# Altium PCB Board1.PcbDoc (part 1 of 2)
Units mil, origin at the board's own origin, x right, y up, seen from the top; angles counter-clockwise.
Board outline 6000 x 4000 mil, 8 copper layers (Top Layer, 3.3V, 2.5V, 1.8V, 1.0V, GND, signal2, Bottom Layer), stack 66.302 mil thick; 90 components, 131 nets, 720 pads, 306 vias.
Unrouted connection lines stored in the file: 162.
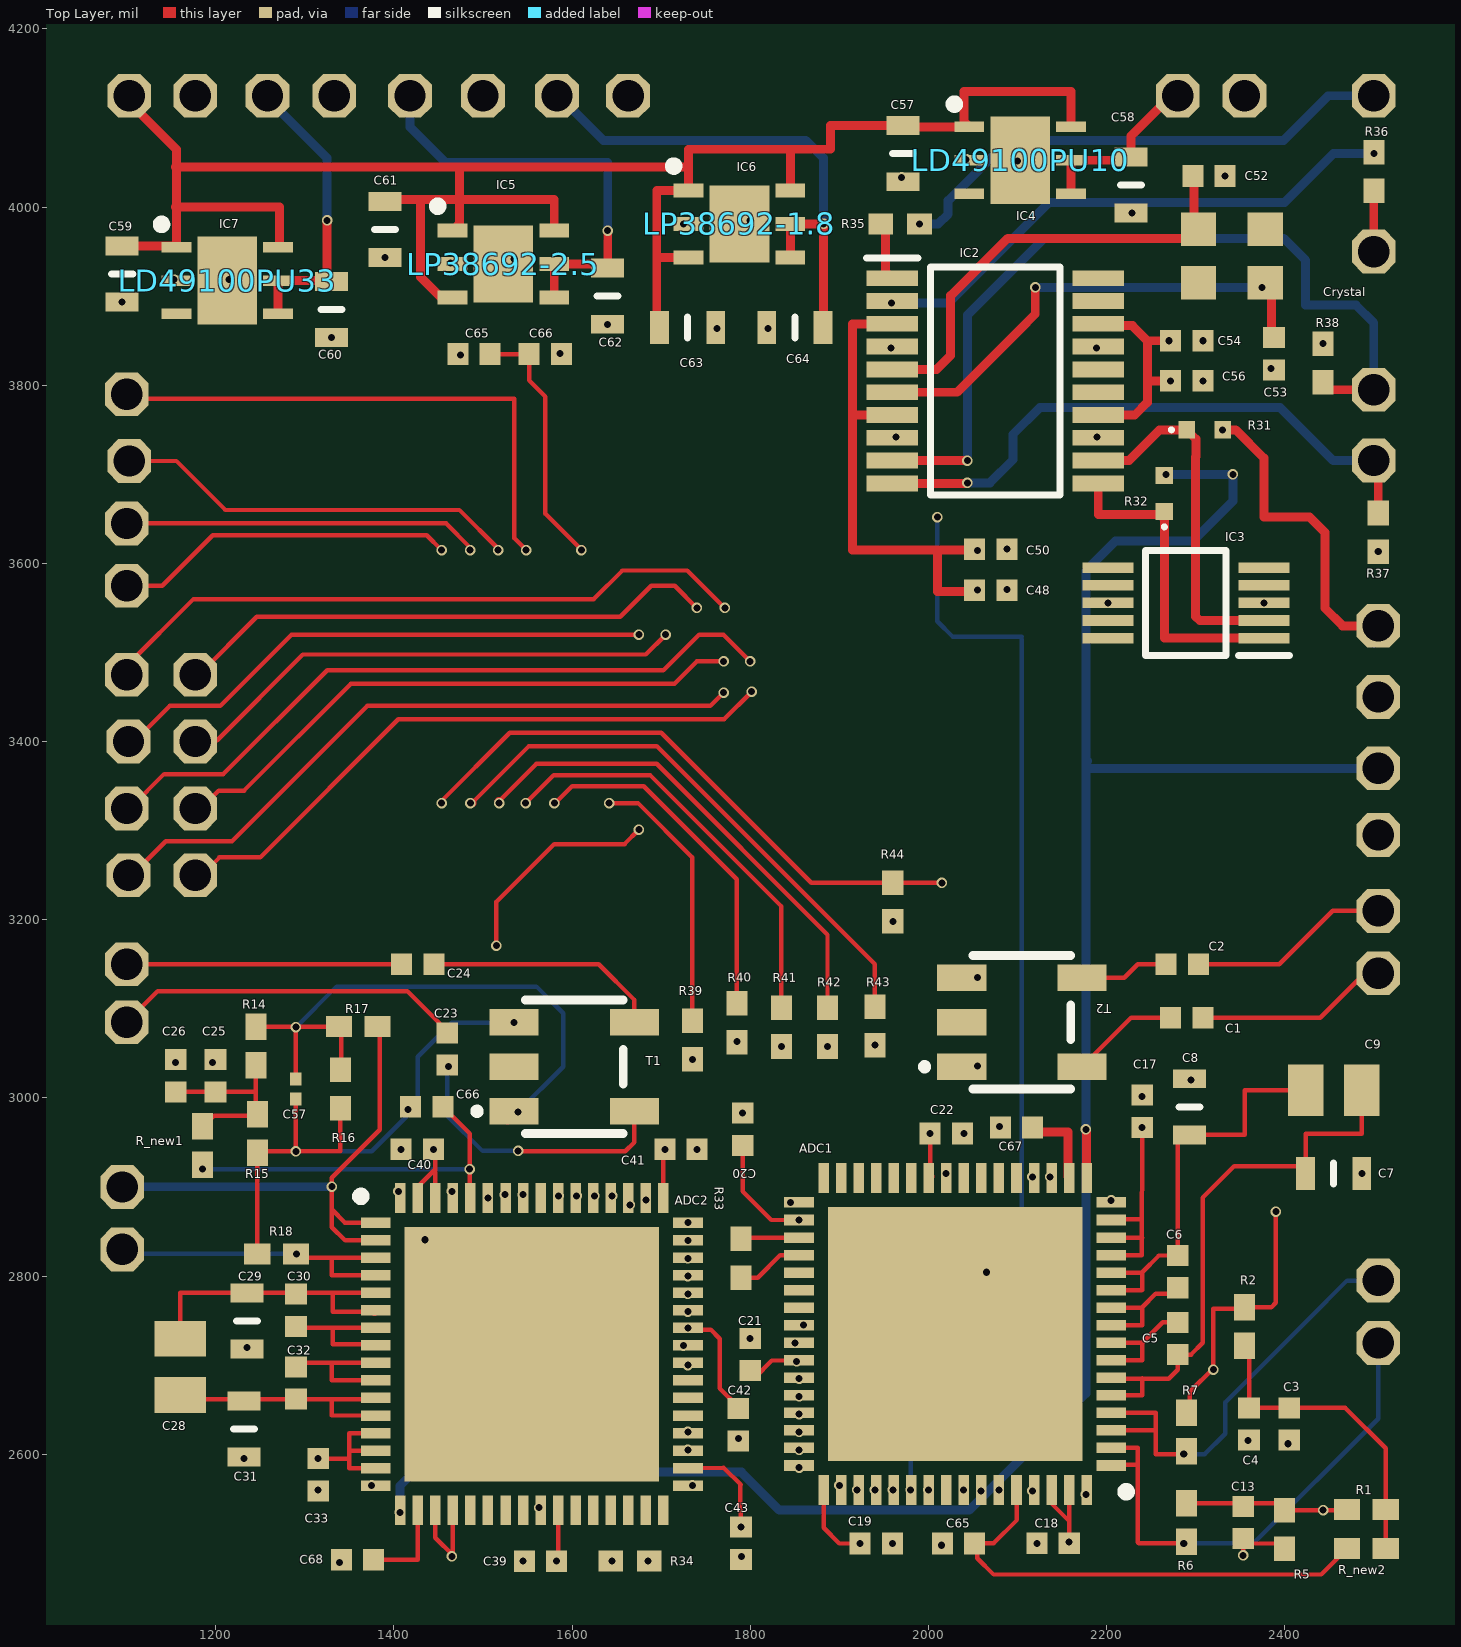
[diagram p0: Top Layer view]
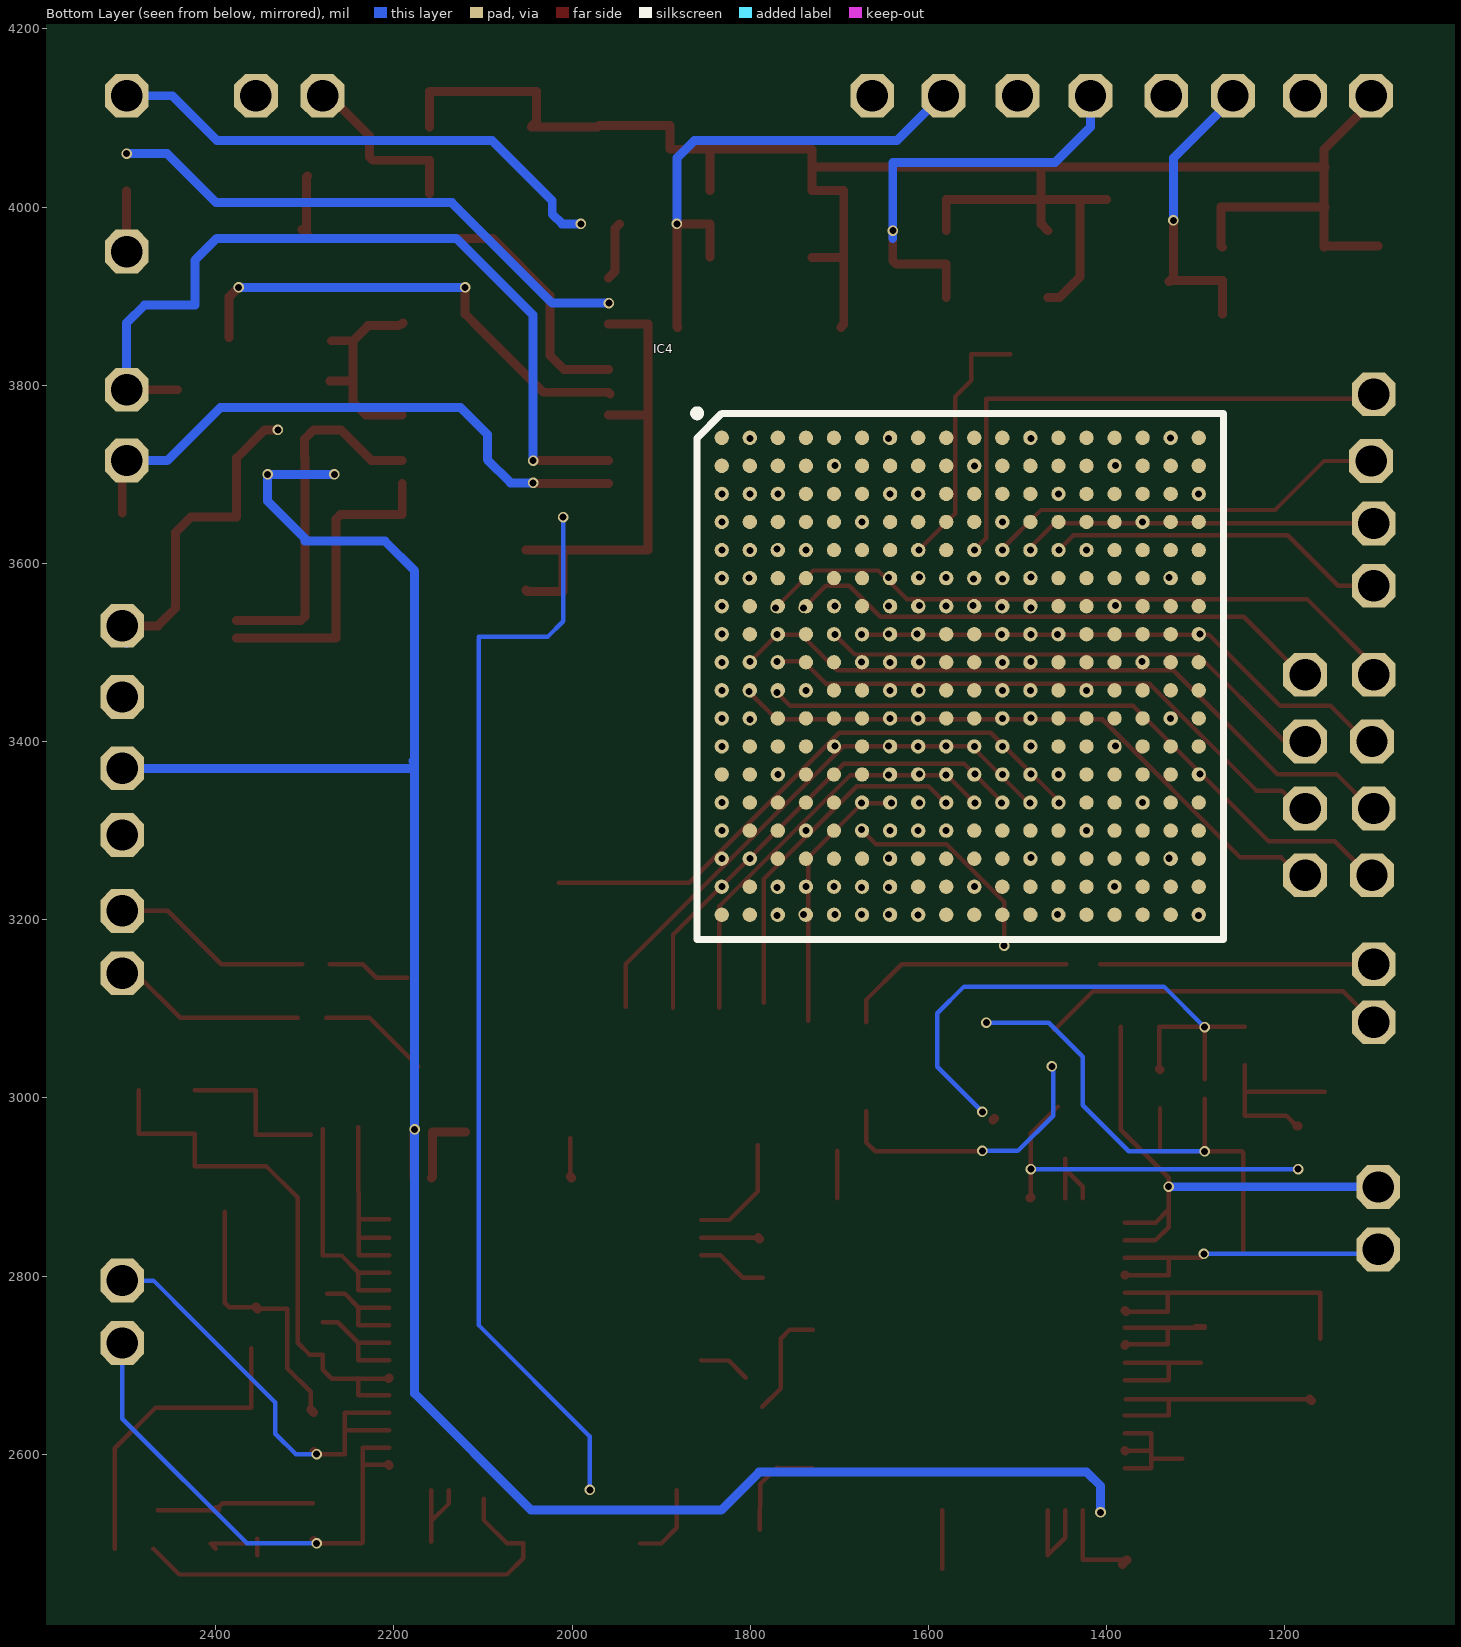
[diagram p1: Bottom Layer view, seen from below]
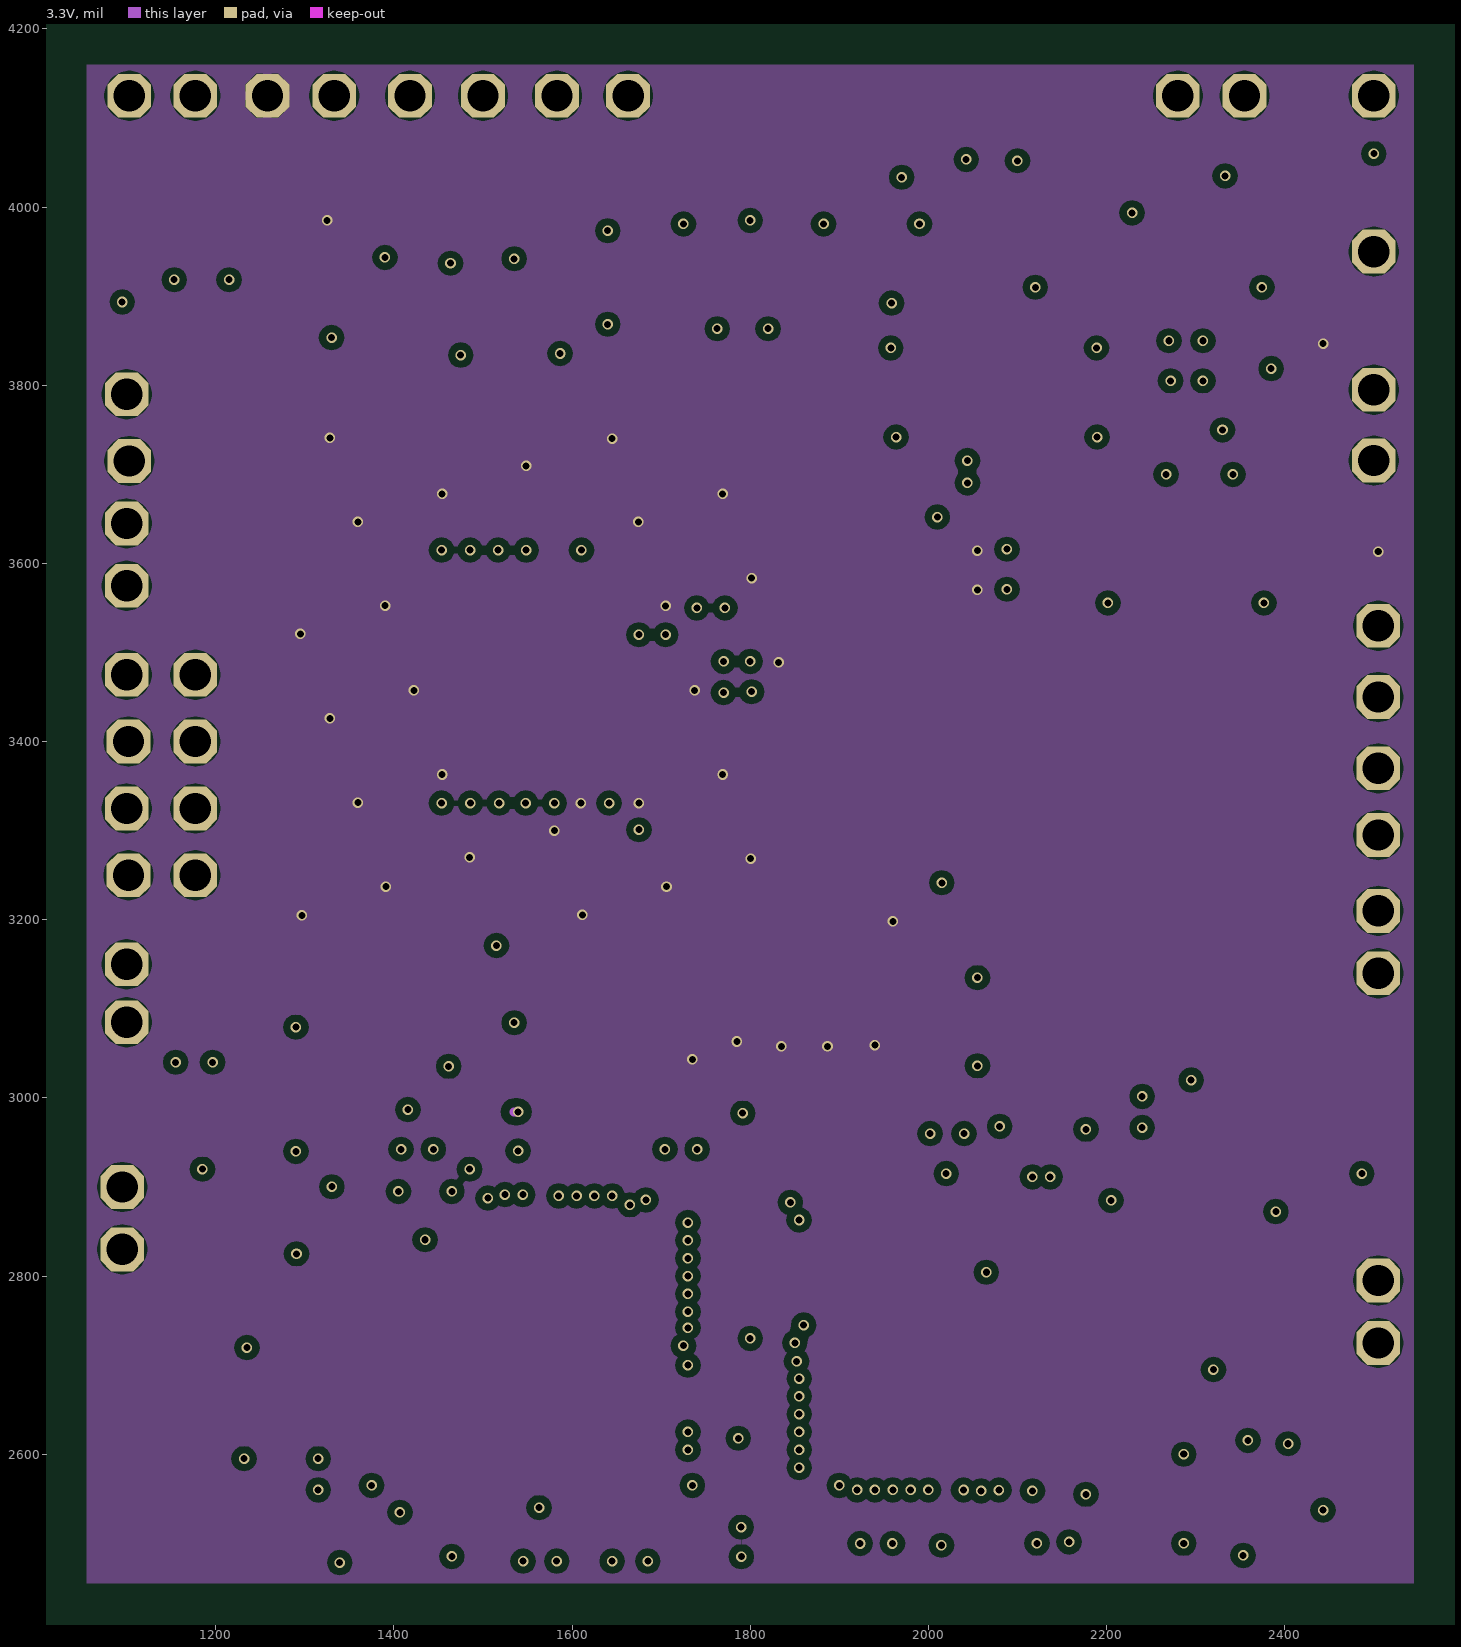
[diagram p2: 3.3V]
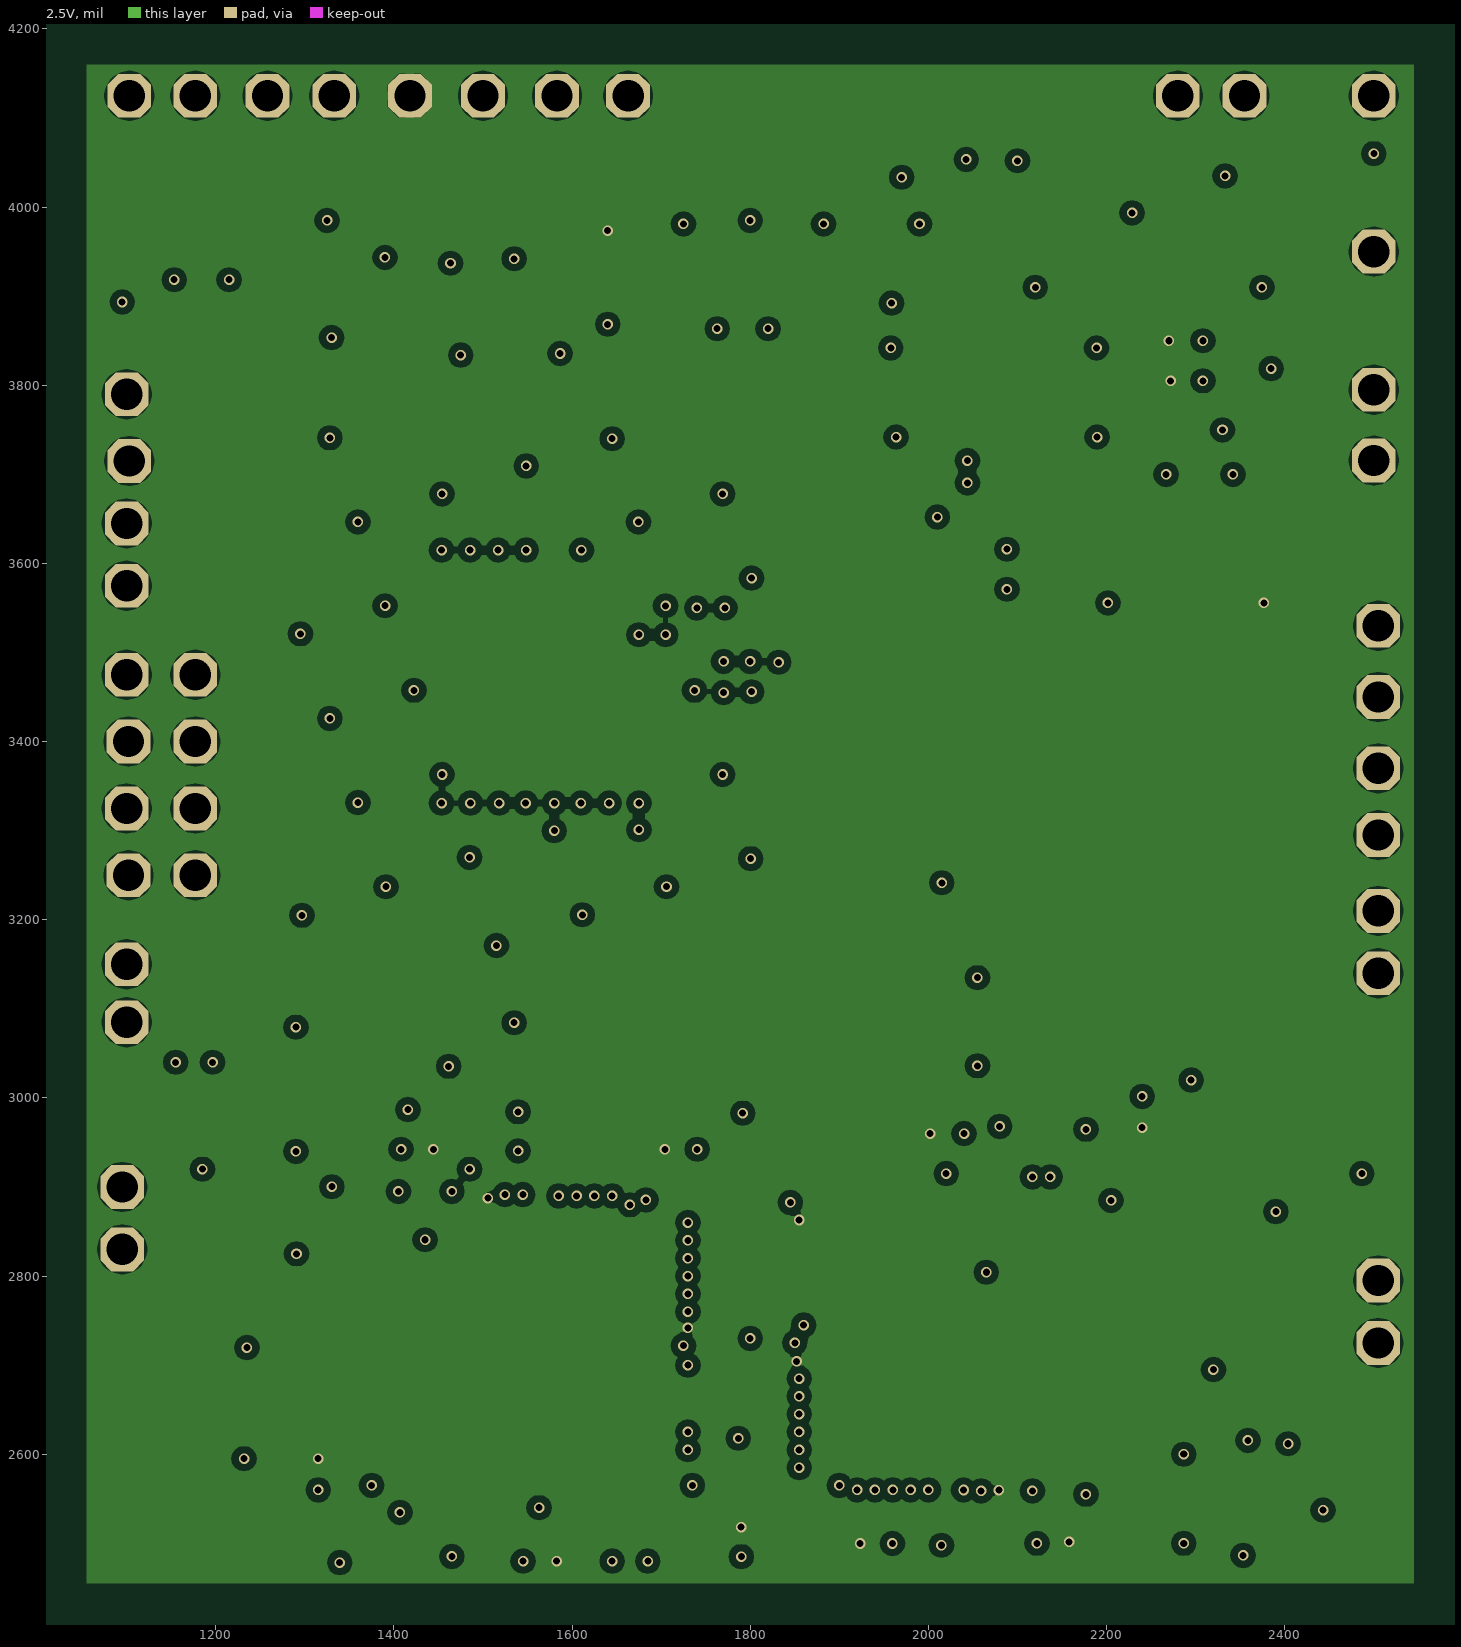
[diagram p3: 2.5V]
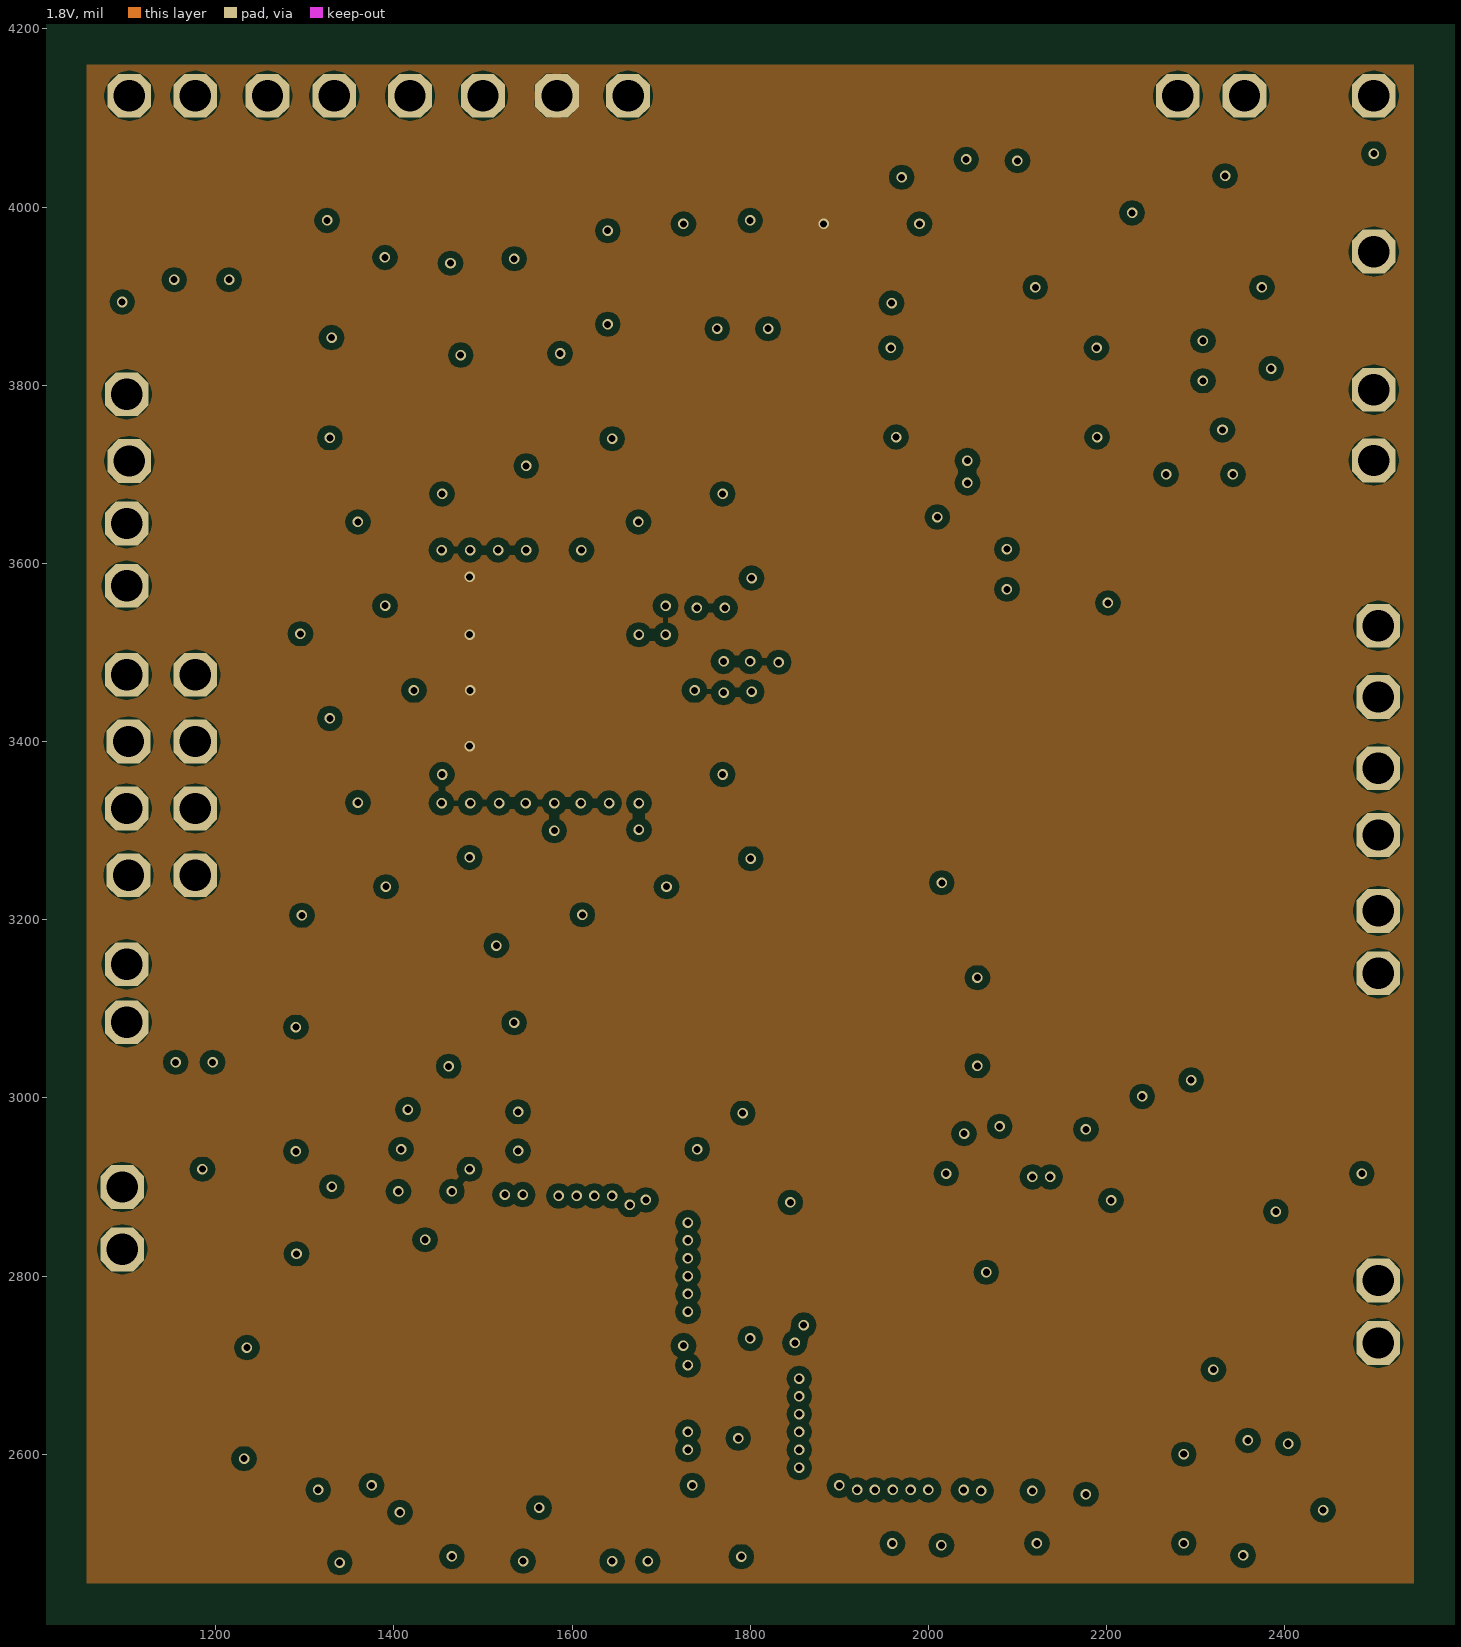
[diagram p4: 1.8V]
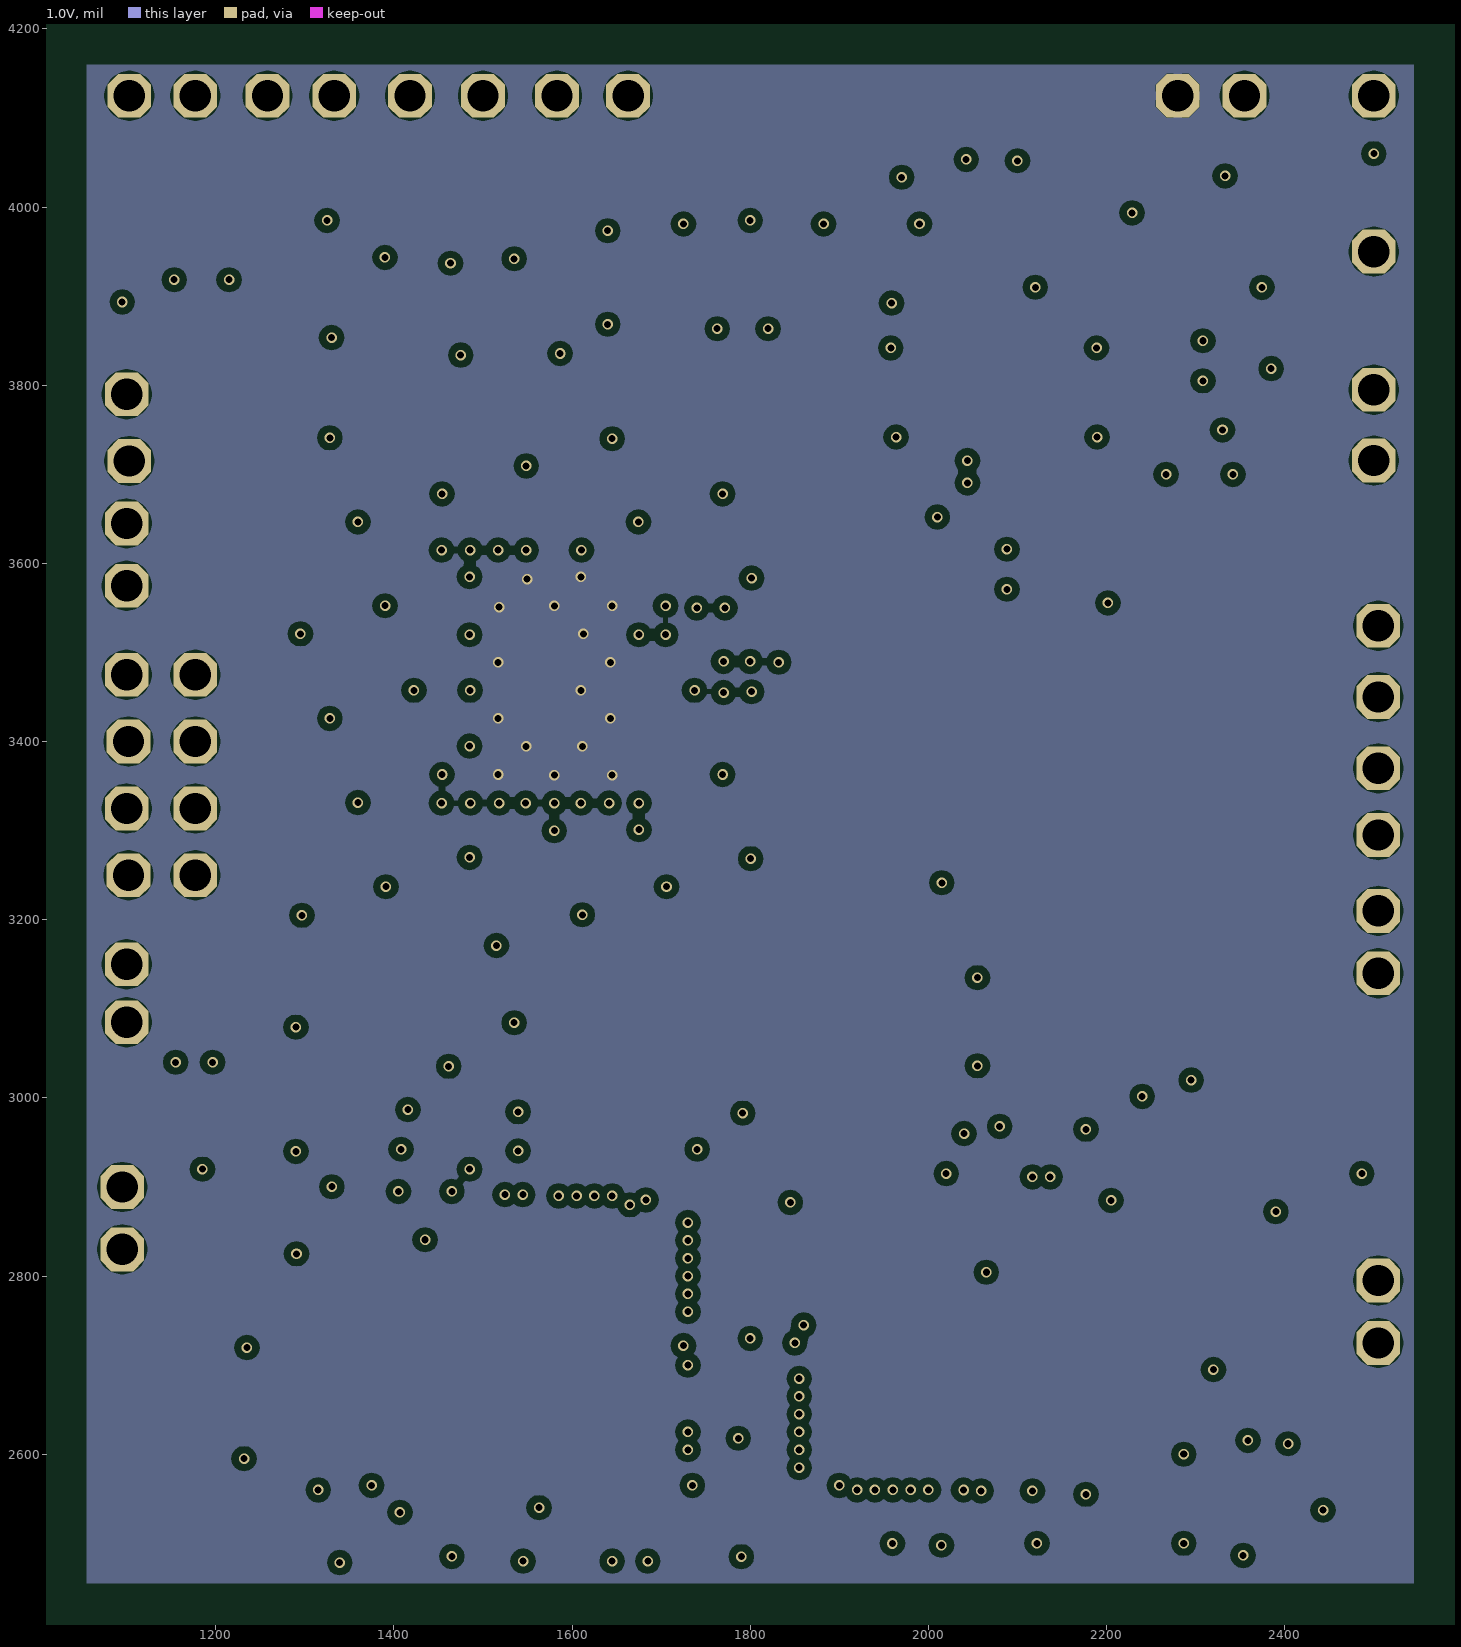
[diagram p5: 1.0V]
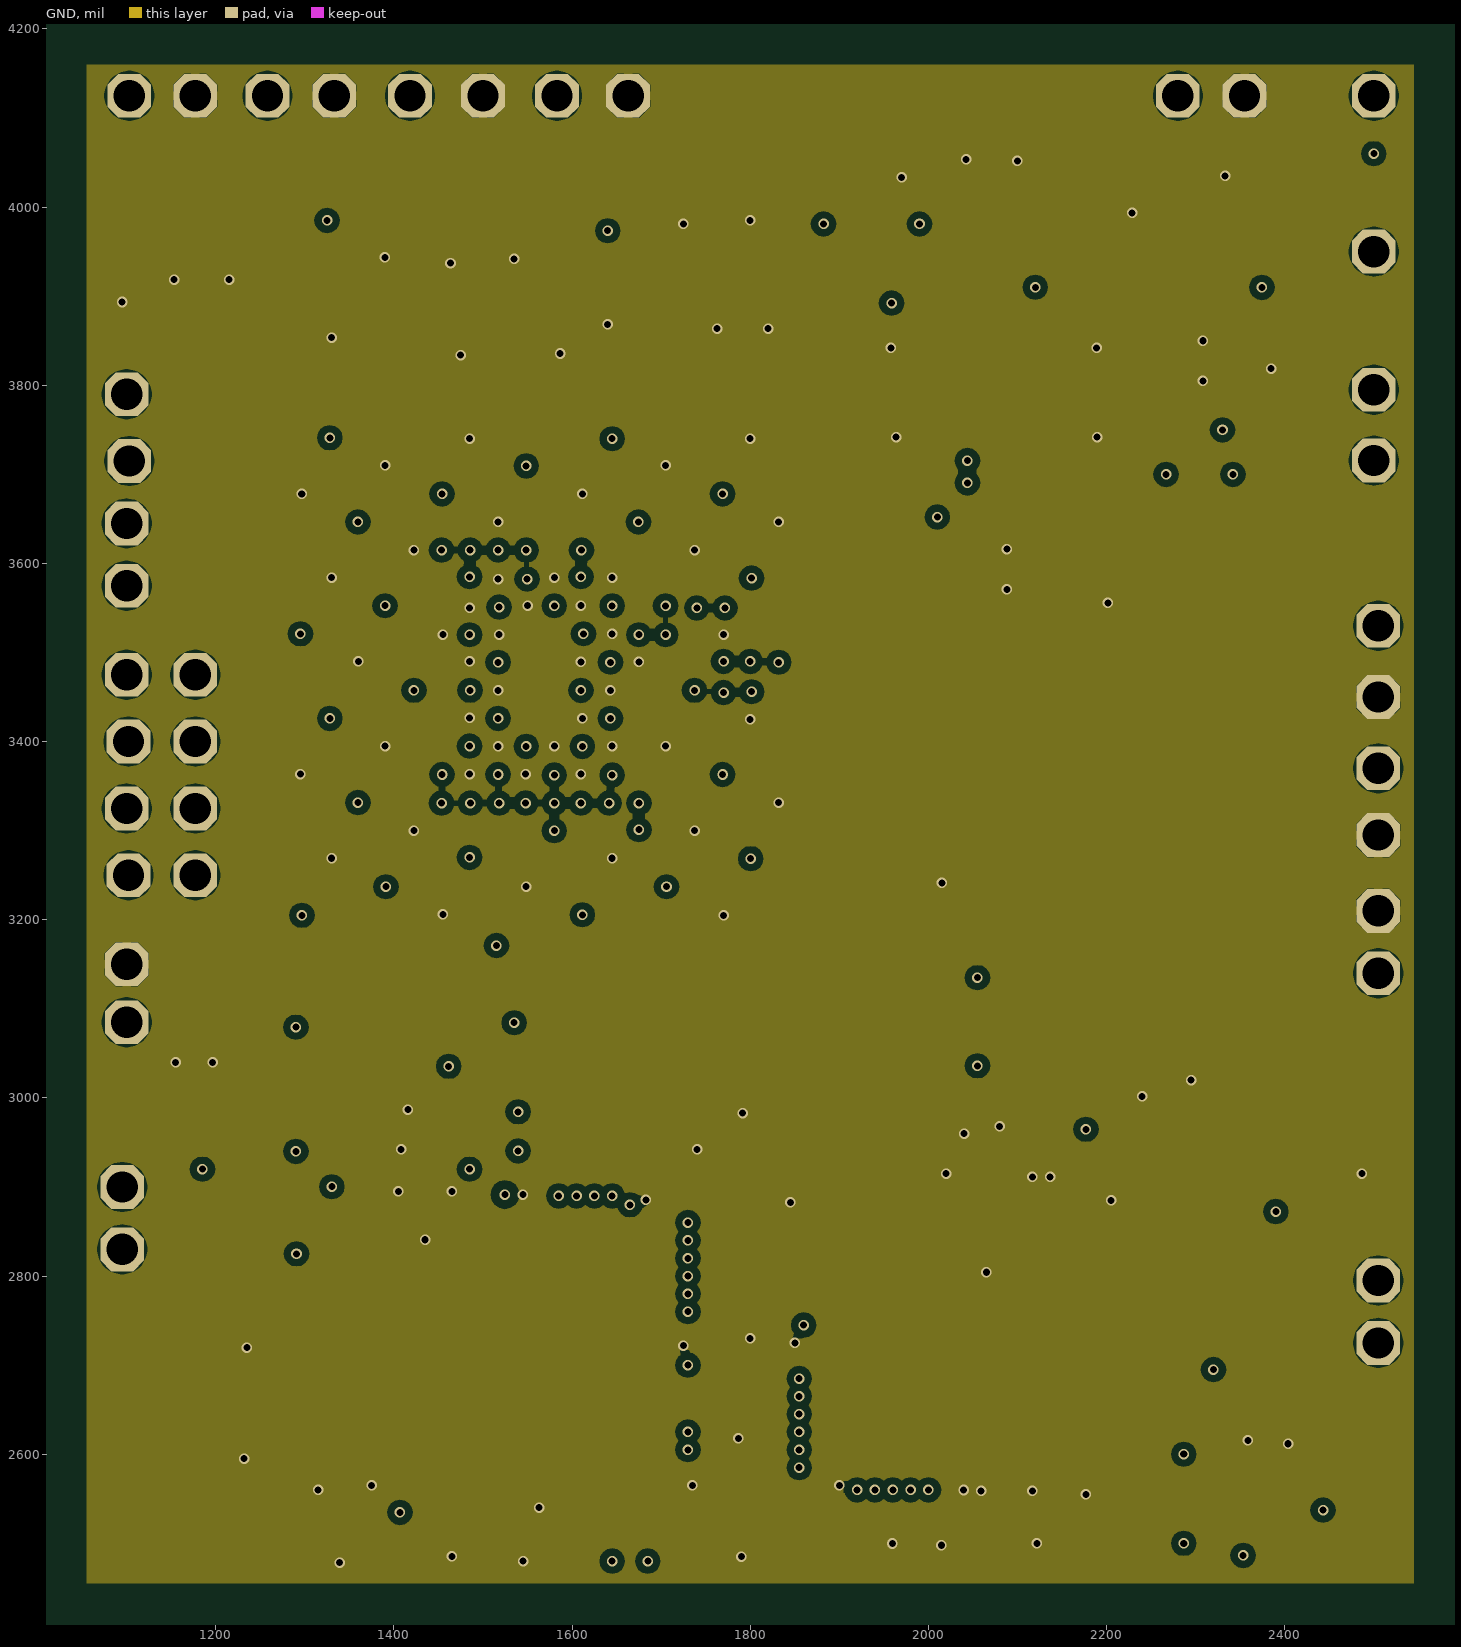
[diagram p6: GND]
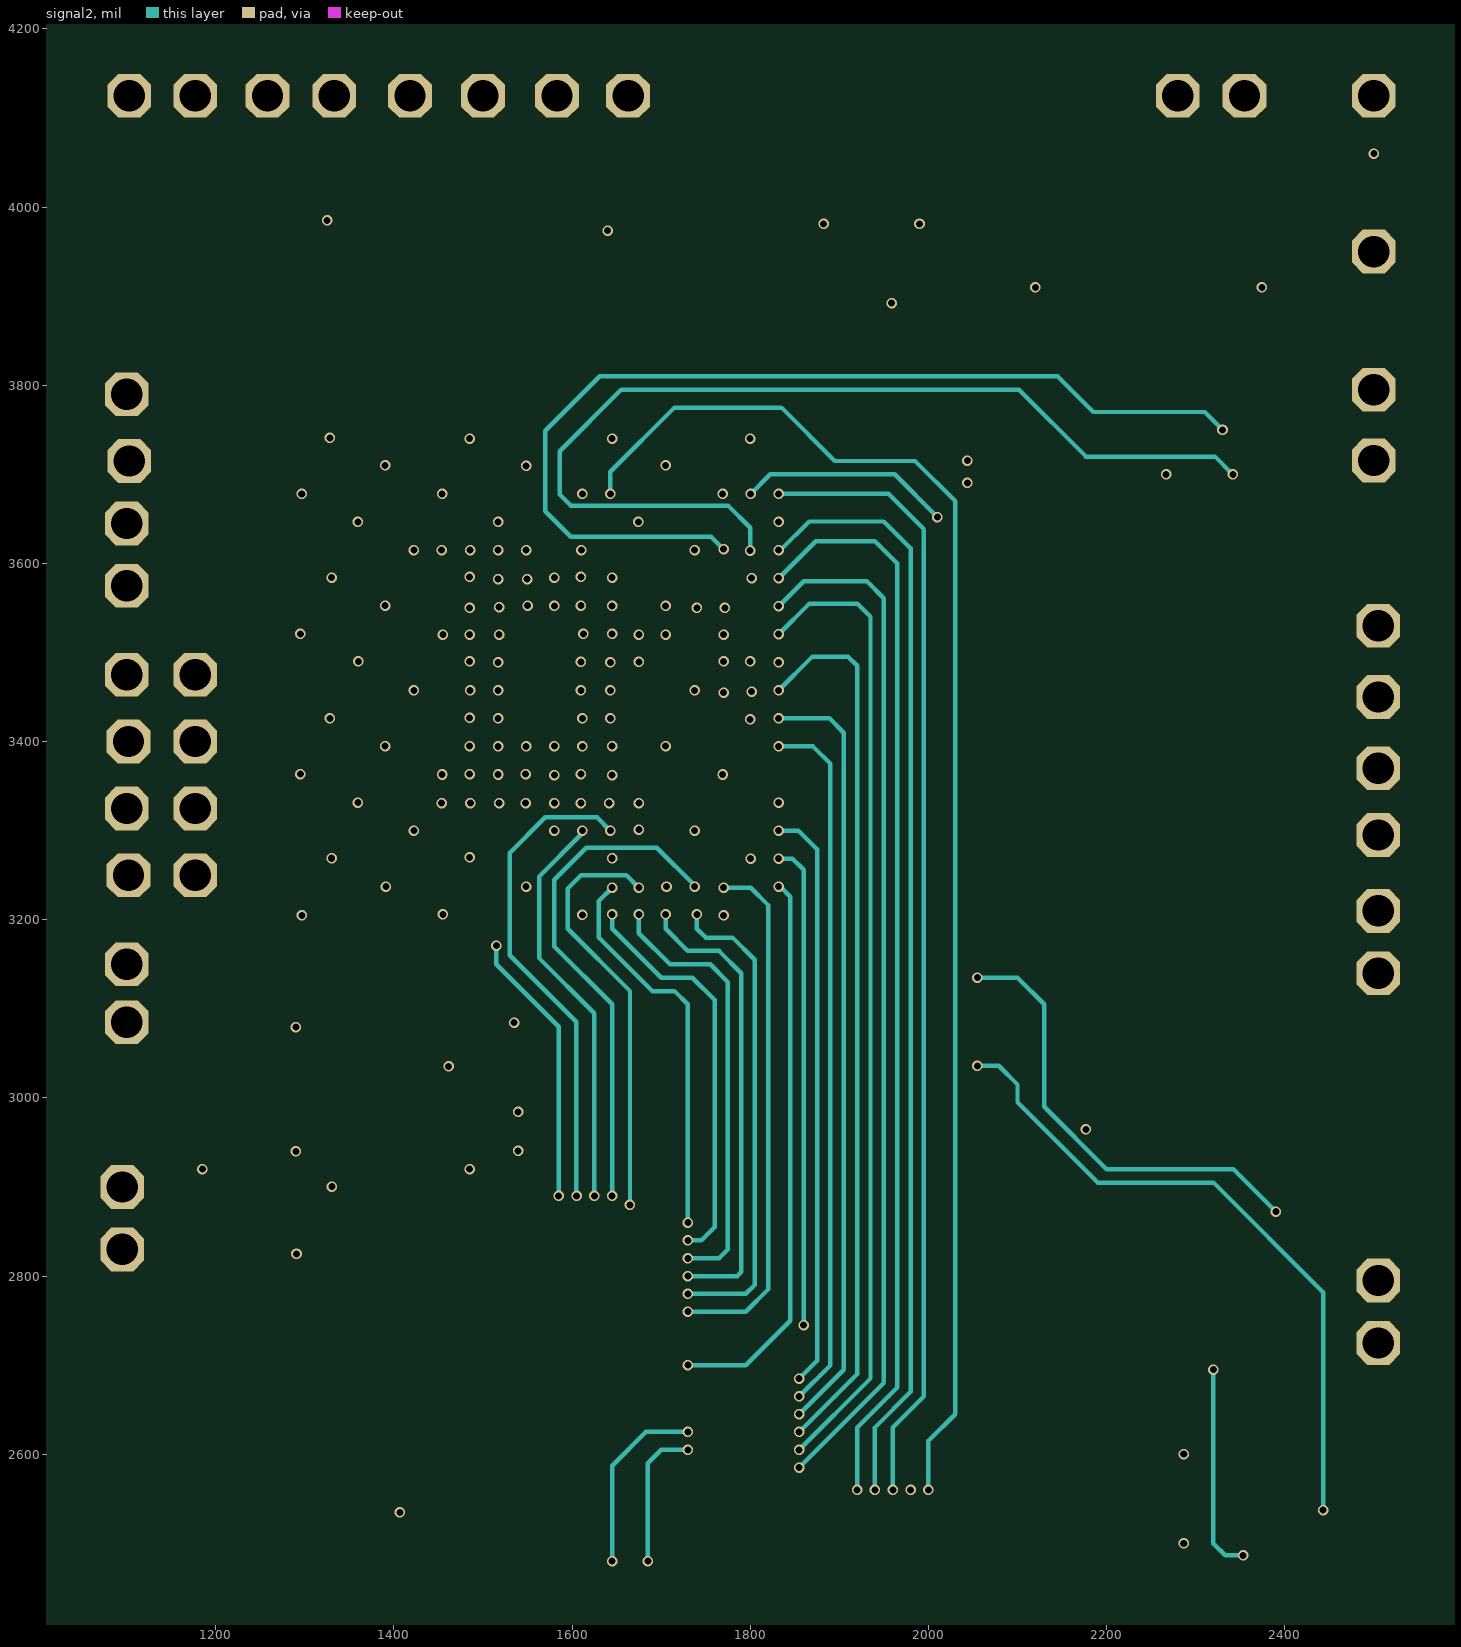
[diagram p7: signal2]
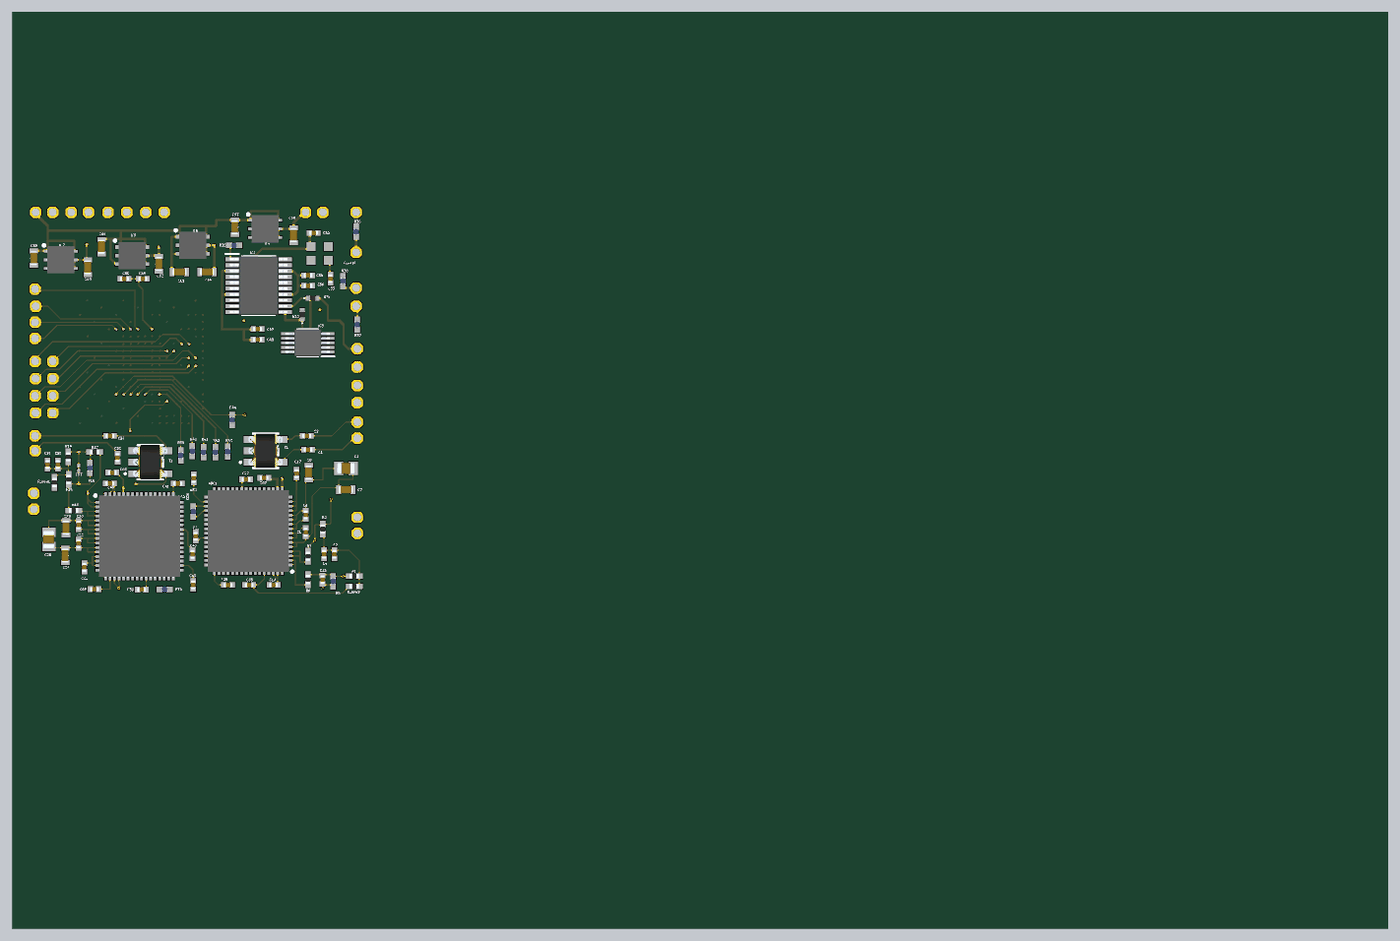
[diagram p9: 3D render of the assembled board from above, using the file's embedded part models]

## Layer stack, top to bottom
Top Solder: solder mask 0.4, Solder Resist, Dk 3.5
Top Layer: signal copper 1.4
Dielectric 1: core 10, FR-4, Dk 4.2
3.3V: signal copper 1.417
Dielectric 3: prepreg 5, Dk 4.2
2.5V: signal copper 1.417
Dielectric 4: core 10, Dk 4.2
1.8V: signal copper 1.417
Dielectric 5: prepreg 5, Dk 4.2
1.0V: signal copper 1.417
Dielectric 6: core 10, Dk 4.2
GND: signal copper 1.417
Dielectric 7: prepreg 5, Dk 4.2
signal2: signal copper 1.417
Dielectric 2: core 10, Dk 4.2
Bottom Layer: signal copper 1.4
Bottom Solder: solder mask 0.4, Solder Resist, Dk 3.5

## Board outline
1000,1000 7000,1000 7000,5000 1000,5000

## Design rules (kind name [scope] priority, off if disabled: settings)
AssemblyTestPointUsage [All] p1 off:
AssemblyTestpoint [All] p1 off: testpointundercomponent=TRUE minsize=40 maxsize=100 preferedsize=60 minholesize=0 maxholesize=40 preferedholesize=32 testpointgrid=1 usegrid=TRUE gridtolerance=0.01 allowsidetop=TRUE allowsidebottom=TRUE
Clearance Clearance_9 [InNamedPolygon('3.3V_L02_P032')] p1: gap=10 ignorepadtopadclearanceinfootprint=FALSE
Clearance Clearance_8 [InNamedPolygon('3.3V_L02_P032')] p2: gap=5 ignorepadtopadclearanceinfootprint=FALSE
Clearance Clearance_7 [InNamedPolygon('GND_L06_P040') Or  InNamedPolygon('1.0V_L05_P038') Or  InNamedPolygon('1.8V_L04_P036') Or  InNamedPolygon('3.3V_L02_P032') Or  InNamedPolygon('2.5V_L03_P034')] p3: gap=10 ignorepadtopadclearanceinfootprint=FALSE except(0: Arc-Hole Track-Hole SMDPad-Hole THPad-Hole Via-Hole Fill-Hole Poly-Hole Region-Hole Text-Hole)
Clearance Clearance_6 [InNamedPolygon('2.5V_L03_P034')] p4: gap=10 ignorepadtopadclearanceinfootprint=FALSE except(0: Arc-Hole Track-Hole SMDPad-Hole THPad-Hole Via-Hole Fill-Hole Poly-Hole Region-Hole Text-Hole)
Clearance Clearance_5 [InNamedPolygon('1.8V_L04_P036') Or  InNamedPolygon('2.5V_L03_P034') Or  InNamedPolygon('GND_L06_P040') Or  InNamedPolygon('1.0V_L05_P038') Or  InNamedPolygon('3.3V_L02_P032')] p5: gap=2 ignorepadtopadclearanceinfootprint=FALSE
Clearance Clearance_4 [InNamedPolygon('1.8V_L04_P036') Or  InNamedPolygon('2.5V_L03_P034') Or  InNamedPolygon('GND_L06_P040') Or  InNamedPolygon('1.0V_L05_P038') Or  InNamedPolygon('3.3V_L02_P032')] p6: gap=10 ignorepadtopadclearanceinfootprint=FALSE except(0: Arc-Hole Track-Hole SMDPad-Hole THPad-Hole Via-Hole Fill-Hole Poly-Hole Region-Hole Text-Hole)
Clearance Clearance_3 [InNamedPolygon('2.5V_L03_P034')] p7: gap=10 ignorepadtopadclearanceinfootprint=FALSE except(0: Arc-Hole Track-Hole SMDPad-Hole THPad-Hole Via-Hole Fill-Hole Poly-Hole Region-Hole Text-Hole)
Clearance Clearance_2 [InNamedPolygon('2.5V_L03_P034')] p8: gap=2 ignorepadtopadclearanceinfootprint=FALSE
Clearance Clearance_1 [InNamedPolygon('1.0V_L05_P038')] p9: gap=10 ignorepadtopadclearanceinfootprint=FALSE except(0: Arc-Hole Track-Hole SMDPad-Hole THPad-Hole Via-Hole Fill-Hole Poly-Hole Region-Hole Text-Hole)
Clearance [All] p10 off: gap=10 ignorepadtopadclearanceinfootprint=FALSE except(0: Arc-Hole Track-Hole SMDPad-Hole THPad-Hole Via-Hole Fill-Hole Poly-Hole Region-Hole Text-Hole)
ComponentClearance [All] p1 off: gap=10 collisioncheckmode=3 verticalgap=10 showdistances=FALSE
DiffPairsRouting [All] p1 off: maxlimit=10 minlimit=10 mostfreqgap=10 toplayer_minwidth=15 toplayer_maxwidth=15 toplayer_prefwidth=15 midlayer1_minwidth=15 midlayer1_maxwidth=15 midlayer1_prefwidth=15 midlayer2_minwidth=15 midlayer2_maxwidth=15 midlayer2_prefwidth=15 midlayer3_minwidth=15 midlayer3_maxwidth=15 midlayer3_prefwidth=15 midlayer4_minwidth=15 midlayer4_maxwidth=15 midlayer4_prefwidth=15 midlayer5_minwidth=15 midlayer5_maxwidth=15 midlayer5_prefwidth=15 midlayer6_minwidth=15 midlayer6_maxwidth=15 midlayer6_prefwidth=15 bottomlayer_minwidth=15 bottomlayer_maxwidth=15 bottomlayer_prefwidth=15 maxuncoupledlength=500
FabricationTestPointUsage [All] p1 off: valid=0 allowmultiple=FALSE
FabricationTestpoint [All] p1 off: side=3 testpointundercomponent=TRUE minsize=40 maxsize=100 preferedsize=60 minholesize=0 maxholesize=40 preferedholesize=32 testpointgrid=1 allowsidetop=TRUE allowsidebottom=TRUE usegrid=TRUE gridtolerance=0.01
FanoutControl Fanout_BGA [IsBGA] p1 off: bgadir=Out bgaviamode=Centered fanoutstyle=Auto fanoutdirection=Alternating viagrid=1 // Fanout_BGA (Default Rule)
FanoutControl Fanout_LCC [IsLCC] p2 off: bgadir=Out bgaviamode=Centered fanoutstyle=Auto fanoutdirection=Alternating viagrid=1 // Fanout_LCC (Default Rule)
FanoutControl Fanout_SOIC [IsSOIC] p3 off: bgadir=Out bgaviamode=Centered fanoutstyle=Auto fanoutdirection=Alternating viagrid=1 // Fanout_SOIC (Default Rule)
FanoutControl Fanout_Small [(CompPinCount < 5)] p4 off: bgadir=Out bgaviamode=Centered fanoutstyle=Auto fanoutdirection=OutThenIn viagrid=1 // Fanout_Small (Default Rule)
Height [All] p1 off: minheight=0 maxheight=1000 prefheight=500
HoleSize [All] p1 off: absolutevalues=TRUE maxlimit=100 minlimit=1 maxpercent=80.000 minpercent=20.000
HoleToHoleClearance [All] p1 off: gap=10 allowstackedmicrovias=TRUE
LayerPairs [All] p1 off: enforce=TRUE
MinimumSolderMaskSliver [All] p1 off: minsoldermaskwidth=10
NetAntennae [All] p1 off: netantennaetolerance=0
PasteMaskExpansion [All] p1 off: expansion=0
PlaneClearance [All] p1 off: clearance=20
PlaneConnect [All] p1 off: planeconnectstyle=Relief reliefexpansion=20 reliefentries=4 reliefconductorwidth=10 reliefairgap=10
PolygonConnect [All] p1 off: connectstyle=Relief reliefconductorwidth=10 reliefentries=4 polygonreliefangle="90 Angle" airgapwidth=10
RoutingCorners [All] p1 off: cornerstyle=45-Degree minsetback=100 maxsetback=100
RoutingLayers [All] p1 off: top layer_v5=TRUE mid layer 1_v5=TRUE mid layer 2_v5=TRUE mid layer 3_v5=TRUE mid layer 4_v5=TRUE mid layer 5_v5=TRUE mid layer 6_v5=TRUE bottom layer_v5=TRUE
RoutingPriority [All] p1 off: routingpriority=0
RoutingTopology [All] p1 off: topology=Shortest
RoutingVias [All] p1 off: holewidth=28 width=50 viastyle="Through Hole" minholewidth=28 minwidth=50 maxholewidth=28 maxwidth=50
ShortCircuit [All] p1 off: allowed=FALSE
SilkToSilkClearance [All] p1 off: silktosilkclearance=10
SilkToSolderMaskClearance [IsPad] p1 off: minsilkscreentomaskgap=10 clearancetoexposedcopper=TRUE
SolderMaskExpansion [All] p1 off: expansion=4
UnRoutedNet [All] p1 off:
UnpouredPolygon [All] p1 off:
Width [All] p1 off: maxlimit=10 minlimit=10 preferedwidth=10
1 further rules are at their usual default settings.

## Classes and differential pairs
component class Schematic1: * *? ? IC4 "Input power?" VDD?

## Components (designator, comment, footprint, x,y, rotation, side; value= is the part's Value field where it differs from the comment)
ADC1 "LTC2242CUP-12" QFN50P900X900X80-65N-D 2030,2735 r180 top locked
ADC2 "LTC2242CUP-12" QFN50P900X900X80-65N-D 1554.8,2712.36 r0 top locked
C1 "Comment" CAPC1005X55N 2290,3090 r0 top locked
C2 "Comment" CAPC1005X55N 2285,3150 r0 top locked
C3 "Comment" CAPC1005X55N 2405,2633.86 r90 top locked
C4 "Comment" CAPC1005X55N 2360,2633.86 r90 top locked
C5 "0.1uF" CAPC1005X55N 2280,2730 r270 top locked (schematic designator C6)
C6 "0.1uF" CAPC1005X55N 2280,2805 r270 top locked
C7 "1uF" CAPC1608X90N 2455,2915 r180 top locked (schematic designator C8)
C8 "1uF" CAPC1608X90N 2293.35,2990 r90 top locked
C9 "Comment" CAPC2012X145N 2455,3008.54 r0 top locked
C13 "Comment" CAPC1005X55N 2353.35,2523.27 r90 top locked
C17 "0.1uF" CAPC1005X55N 2240.16,2985 r270 top locked
C18 "Comment" CAPC1005X55N 2140,2500 r0 top locked
C19 "Comment" CAPC1005X55N 1941.42,2499.8 r0 top locked
C20 "0.1uF" CAPC1005X55N 1791.57,2964.76 r270 top locked
C21 "0.1uF" CAPC1005X55N 1800,2711.89 r270 top locked
C22 "0.1uF" CAPC1005X55N 2020,2960 r180 top locked
C23 "Comment" CAPC1005X55N 1460,3055 r90 top locked
C24 "Comment" CAPC1005X55N 1426.85,3150 r0 top locked
C25 "0.1uF" CAPC1005X55N 1199.76,3025 r270 top locked
C26 "0.1uF" CAPC1005X55N 1155,3025 r270 top locked
C28 "2.2uF" CAPC2012X145N 1160,2698.11 r90 top locked
C29 "1uF" CAPC1608X90N 1235,2749.68 r90 top locked
C30 "0.1uF" CAPC1005X55N 1290,2761.57 r90 top locked
C31 "1uF" CAPC1608X90N 1231.73,2628.5 r270 top locked
C32 "0.1uF" CAPC1005X55N 1290,2680 r90 top locked
C33 "0.1uF" CAPC1005X55N 1315,2576.89 r90 top locked
C39 "0.1uF" CAPC1005X55N 1564.65,2480 r0 top locked
C40 "Comment" CAPC1005X55N 1426.1,2942.36 r0 top locked
C41 "Comment" CAPC1005X55N 1722.32,2942.36 r0 top locked
C42 "0.1uF" CAPC1005X55N 1786.57,2633.18 r90 top locked
C43 "0.1uF" CAPC1005X55N 1789.75,2500 r90 top locked
C48 "Comment" CAPC1005X55N 2070,3570 r0 top locked
C50 "Comment" CAPC1005X55N 2070,3615.98 r0 top locked
C52 "17pF" CAPC1005X55N 2315,4035 r180 top locked (schematic designator C54)
C53 "17pF" CAPC1005X55N 2387.91,3835.28 r90 top (schematic designator C54)
C54 "100nF" CAPC1005X55N 2290,3850 r180 top locked
C56 "Comment" CAPC1005X55N 2290,3805 r0 top locked
C57 "Comment" CAPC0402X22N 1290,3010 r90 top locked
C57 "1uF" CAPC1608X90N 1971.5,4060 r90 top locked
C58 "1uF" CAPC1608X90N 2227.52,4025 r90 top locked
C59 "1uF" CAPC1608X90N 1095,3925 r90 top locked
C60 "1uF" CAPC1608X90N 1330,3885 r90 top locked
C61 "1uF" CAPC1608X90N 1389.96,3975 r90 top locked
C62 "1uF" CAPC1608X90N 1640,3900 r90 top locked
C63 "1uF" CAPC1608X90N 1729.8,3865 r0 top locked
C64 "1uF" CAPC1608X90N 1850,3865 r0 top locked
C65 "2.2uF" CAPC1005X55N 2033.78,2499.8 r180 top locked
C65 "0.1uF" CAPC1005X55N 1490,3835 r0 top locked
C66 "Comment" CAPC1005X55N 1436.89,2990 r0 top locked
C66 "Comment" CAPC1005X55N 1570,3835 r0 top locked
C67 "Comment" CAPC1005X55N 2098.9,2966.89 r0 top locked
C68 "Comment" CAPC1005X55N 1359.13,2481.46 r180 top locked
Crystal "Comment" PCBComponent_1 2419.53,3870 r0 top locked
IC2 "CDCE906PWR" SOP65P640X120-20N 2075,3805 r0 top locked
IC3 "SP3003-04ATG" SOP50P488X110-10N 2289.06,3555.63 r180 top locked
IC4 "XC7A100T-2CSG324I" BGA324C80P18X18_1500X1500X150 1564.25,3473.31 r180 bottom locked
LD49100PU10 "IC4" SON95P300X300X90-7N-D 2102.91,4052.6 r0 top locked
LD49100PU33 "IC7" SON95P300X300X90-7N-D 1212.91,3917.6 r0 top locked
LP38692-1.8 "IC6" SON95P300X300X80-7N 1787.91,3981.1 r0 top locked
LP38692-2.5 "IC5" SON95P300X300X80-7N 1522.91,3936.1 r0 top locked
R1 "49.9ohm" RESC1005X40N 2491.61,2538.11 r180 top
R2 "49.9ohm" RESC1005X40N 2355,2743.46 r270 top locked
R5 "Comment" RESC1005X37N 2400,2515.63 r90 top locked
R6 "4.99ohm" RESC1005X40N 2290,2523.27 r270 top locked
R7 "4.99ohm" RESC1005X40N 2290,2625 r270 top locked
R14 "49.9ohm" RESC1005X40N 1245,3058.35 r90 top locked
R15 "49.9ohm" RESC1005X40N 1246.69,2960 r90 top locked
R16 "100ohm" RESC1005X37N 1340,3010 r90 top locked
R17 "4.99ohm" RESC1005X40N 1360,3080 r0 top locked
R18 "4.99ohm" RESC1005X40N 1268.35,2825 r0 top locked
R31 "22ohm" H2C/H2R 2310.16,3750 r0 top locked
R32 "10ohm" H2C/H2R 2264.84,3678.5 r90 top locked
R33 "Comment" RESC1005X37N 1789.4,2820 r270 top locked
R34 "Comment" RESC1005X37N 1665,2480 r180 top locked
R35 "1.2k" RESC1005X37N 1968.35,3981.1 r0 top locked
R36 "1.2k" RESC1005X37N 2500,4040 r270 top locked
R37 "1.2k" RESC1005X37N 2505,3635 r270 top locked
R38 "1.2k" RESC1005X37N 2443.03,3825 r90 top locked
R39 "Comment" RESC1005X37N 1735,3065 r90 top locked
R40 "Comment" RESC1005X37N 1785,3084.4 r90 top locked
R41 "Comment" RESC1005X37N 1835,3079.4 r90 top locked
R42 "Comment" RESC1005X37N 1886.73,3079.4 r90 top locked
R43 "Comment" RESC1005X37N 1940,3080.9 r90 top locked
R44 "Comment" RESC1005X37N 1960,3219.84 r90 top locked
R_new1 "49.9ohm" RESC1005X40N 1185,2946.65 r90 top locked (schematic designator R15)
R_new2 "49.9ohm" RESC1005X40N 2491.61,2493.98 r180 top locked (schematic designator R15)
T1 "MABA-007159" E_SERIES_1 1602.48,3035 r180 top locked
T2 "MABA-007159" E_SERIES_1 2105,3085 r180 top locked

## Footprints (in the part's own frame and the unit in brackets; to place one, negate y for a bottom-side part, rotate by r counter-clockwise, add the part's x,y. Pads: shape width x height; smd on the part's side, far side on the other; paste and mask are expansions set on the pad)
BGA324C80P18X18_1500X1500X150 [mm]
  round 0.41 smd: A1(-6.8,6.8) A2(-6,6.8) A3(-5.2,6.8) A4(-4.4,6.8) A5(-3.6,6.8) A6(-2.8,6.8) A7(-2,6.8) A8(-1.2,6.8) A9(-0.4,6.8) A10(0.4,6.8) A11(1.2,6.8) A12(2,6.8) A13(2.8,6.8) A14(3.6,6.8) A15(4.4,6.8) A16(5.2,6.8) A17(6,6.8) A18(6.8,6.8) B1(-6.8,6) B2(-6,6) B3(-5.2,6) B4(-4.4,6) B5(-3.6,6) B6(-2.8,6) B7(-2,6) B8(-1.2,6) B9(-0.4,6) B10(0.4,6) B11(1.2,6) B12(2,6) B13(2.8,6) B14(3.6,6) B15(4.4,6) B16(5.2,6) B17(6,6) B18(6.8,6) C1(-6.8,5.2) C2(-6,5.2) C3(-5.2,5.2) C4(-4.4,5.2) C5(-3.6,5.2) C6(-2.8,5.2) C7(-2,5.2) C8(-1.2,5.2) C9(-0.4,5.2) C10(0.4,5.2) C11(1.2,5.2) C12(2,5.2) C13(2.8,5.2) C14(3.6,5.2) C15(4.4,5.2) C16(5.2,5.2) C17(6,5.2) C18(6.8,5.2) D1(-6.8,4.4) D2(-6,4.4) D3(-5.2,4.4) D4(-4.4,4.4) D5(-3.6,4.4) D6(-2.8,4.4) D7(-2,4.4) D8(-1.2,4.4) D9(-0.4,4.4) D10(0.4,4.4) D11(1.2,4.4) D12(2,4.4) D13(2.8,4.4) D14(3.6,4.4) D15(4.4,4.4) D16(5.2,4.4) D17(6,4.4) D18(6.8,4.4) E1(-6.8,3.6) E2(-6,3.6) E3(-5.2,3.6) E4(-4.4,3.6) E5(-3.6,3.6) E6(-2.8,3.6) E7(-2,3.6) E8(-1.2,3.6) E9(-0.4,3.6) E10(0.4,3.6) E11(1.2,3.6) E12(2,3.6) E13(2.8,3.6) E14(3.6,3.6) E15(4.4,3.6) E16(5.2,3.6) E17(6,3.6) E18(6.8,3.6) F1(-6.8,2.8) F2(-6,2.8) F3(-5.2,2.8) F4(-4.4,2.8) F5(-3.6,2.8) F6(-2.8,2.8) F7(-2,2.8) F8(-1.2,2.8) F9(-0.4,2.8) F10(0.4,2.8) F11(1.2,2.8) F12(2,2.8) F13(2.8,2.8) F14(3.6,2.8) F15(4.4,2.8) F16(5.2,2.8) F17(6,2.8) F18(6.8,2.8) G1(-6.8,2) G2(-6,2) G3(-5.2,2) G4(-4.4,2) G5(-3.6,2) G6(-2.8,2) G7(-2,2) G8(-1.2,2) G9(-0.4,2) G10(0.4,2) G11(1.2,2) G12(2,2) G13(2.8,2) G14(3.6,2) G15(4.4,2) G16(5.2,2) G17(6,2) G18(6.8,2) H1(-6.8,1.2) H2(-6,1.2) H3(-5.2,1.2) H4(-4.4,1.2) H5(-3.6,1.2) H6(-2.8,1.2) H7(-2,1.2) H8(-1.2,1.2) H9(-0.4,1.2) H10(0.4,1.2) H11(1.2,1.2) H12(2,1.2) H13(2.8,1.2) H14(3.6,1.2) H15(4.4,1.2) H16(5.2,1.2) H17(6,1.2) H18(6.8,1.2) J1(-6.8,0.4) J2(-6,0.4) J3(-5.2,0.4) J4(-4.4,0.4) J5(-3.6,0.4) J6(-2.8,0.4) J7(-2,0.4) J8(-1.2,0.4) J9(-0.4,0.4) J10(0.4,0.4) J11(1.2,0.4) J12(2,0.4) J13(2.8,0.4) J14(3.6,0.4) J15(4.4,0.4) J16(5.2,0.4) J17(6,0.4) J18(6.8,0.4) K1(-6.8,-0.4) K2(-6,-0.4) K3(-5.2,-0.4) K4(-4.4,-0.4) K5(-3.6,-0.4) K6(-2.8,-0.4) K7(-2,-0.4) K8(-1.2,-0.4) K9(-0.4,-0.4) K10(0.4,-0.4) K11(1.2,-0.4) K12(2,-0.4) K13(2.8,-0.4) K14(3.6,-0.4) K15(4.4,-0.4) K16(5.2,-0.4) K17(6,-0.4) K18(6.8,-0.4) L1(-6.8,-1.2) L2(-6,-1.2) L3(-5.2,-1.2) L4(-4.4,-1.2) L5(-3.6,-1.2) L6(-2.8,-1.2) L7(-2,-1.2) L8(-1.2,-1.2) L9(-0.4,-1.2) L10(0.4,-1.2) L11(1.2,-1.2) L12(2,-1.2) L13(2.8,-1.2) L14(3.6,-1.2) L15(4.4,-1.2) L16(5.2,-1.2) L17(6,-1.2) L18(6.8,-1.2) M1(-6.8,-2) M2(-6,-2) M3(-5.2,-2) M4(-4.4,-2) M5(-3.6,-2) M6(-2.8,-2) M7(-2,-2) M8(-1.2,-2) M9(-0.4,-2) M10(0.4,-2) M11(1.2,-2) M12(2,-2) M13(2.8,-2) M14(3.6,-2) M15(4.4,-2) M16(5.2,-2) M17(6,-2) M18(6.8,-2) N1(-6.8,-2.8) N2(-6,-2.8) N3(-5.2,-2.8) N4(-4.4,-2.8) N5(-3.6,-2.8) N6(-2.8,-2.8) N7(-2,-2.8) N8(-1.2,-2.8) N9(-0.4,-2.8) N10(0.4,-2.8) N11(1.2,-2.8) N12(2,-2.8) N13(2.8,-2.8) N14(3.6,-2.8) N15(4.4,-2.8) N16(5.2,-2.8) N17(6,-2.8) N18(6.8,-2.8) P1(-6.8,-3.6) P2(-6,-3.6) P3(-5.2,-3.6) P4(-4.4,-3.6) P5(-3.6,-3.6) P6(-2.8,-3.6) P7(-2,-3.6) P8(-1.2,-3.6) P9(-0.4,-3.6) P10(0.4,-3.6) P11(1.2,-3.6) P12(2,-3.6) P13(2.8,-3.6) P14(3.6,-3.6) P15(4.4,-3.6) P16(5.2,-3.6) P17(6,-3.6) P18(6.8,-3.6) R1(-6.8,-4.4) R2(-6,-4.4) R3(-5.2,-4.4) R4(-4.4,-4.4) R5(-3.6,-4.4) R6(-2.8,-4.4) R7(-2,-4.4) R8(-1.2,-4.4) R9(-0.4,-4.4) R10(0.4,-4.4) R11(1.2,-4.4) R12(2,-4.4) R13(2.8,-4.4) R14(3.6,-4.4) R15(4.4,-4.4) R16(5.2,-4.4) R17(6,-4.4) R18(6.8,-4.4) T1(-6.8,-5.2) T2(-6,-5.2) T3(-5.2,-5.2) T4(-4.4,-5.2) T5(-3.6,-5.2) T6(-2.8,-5.2) T7(-2,-5.2) T8(-1.2,-5.2) T9(-0.4,-5.2) T10(0.4,-5.2) T11(1.2,-5.2) T12(2,-5.2) T13(2.8,-5.2) T14(3.6,-5.2) T15(4.4,-5.2) T16(5.2,-5.2) T17(6,-5.2) T18(6.8,-5.2) U1(-6.8,-6) U2(-6,-6) U3(-5.2,-6) U4(-4.4,-6) U5(-3.6,-6) U6(-2.8,-6) U7(-2,-6) U8(-1.2,-6) U9(-0.4,-6) U10(0.4,-6) U11(1.2,-6) U12(2,-6) U13(2.8,-6) U14(3.6,-6) U15(4.4,-6) U16(5.2,-6) U17(6,-6) U18(6.8,-6) V1(-6.8,-6.8) V2(-6,-6.8) V3(-5.2,-6.8) V4(-4.4,-6.8) V5(-3.6,-6.8) V6(-2.8,-6.8) V7(-2,-6.8) V8(-1.2,-6.8) V9(-0.4,-6.8) V10(0.4,-6.8) V11(1.2,-6.8) V12(2,-6.8) V13(2.8,-6.8) V14(3.6,-6.8) V15(4.4,-6.8) V16(5.2,-6.8) V17(6,-6.8) V18(6.8,-6.8)
  silkscreen extent -7.6,-7.5 7.5,7.6, body extent -7.5,-7.5 7.5,7.5, height 1.5
CAPC0402X22N [mm]
  rect 0.365x0.33 smd: 1(-0.282,0) 2(0.282,0)
  body extent -0.2,-0.1 0.2,0.1, height 0.22
CAPC1005X55N [mm]
  rect 0.6x0.62 smd: 1(-0.46,0) 2(0.46,0)
  body extent -0.5,-0.25 0.5,0.25, height 0.55
CAPC1608X90N [mm]
  rect 0.54x0.94 smd: 1(-0.8,0) 2(0.8,0)
  silkscreen extent 0,-0.3 0,0.3, body extent -0.8,-0.4 0.8,0.4, height 0.9
CAPC2012X145N [mm]
  rect 1.02x1.47 smd: 1(-0.8,0) 2(0.8,0)
  body extent -1,-0.63 1,0.63, height 1.45
E_SERIES_1 [mm]
  rect 1.4x0.76 smd: 1(1.715,1.27) 2(1.715,0) 3(1.715,-1.27) 4(-1.715,-1.27) 5(-1.715,1.27)
  silkscreen extent -1.4,-1.91 2.84,1.91, body extent -1.91,-1.91 1.91,1.91, height 2.6
H2C/H2R [mm]
  rect 0.475x0.5 smd: 1(-0.512,0) 2(0.512,0)
  silkscreen extent -1,-0.05 -0.9,0.05, body extent -0.5,-0.25 0.5,0.25, height 0.4
PCBComponent_1 [mil]
  rect 39.37x37.4 smd: 1(-116.42,45) 1(-116.42,105) 1(-41.42,45) 1(-41.42,105)
QFN50P900X900X80-65N-D [mm]
  rect 0.85x0.3 smd: 1(-4.45,3.75) 2(-4.45,3.25) 3(-4.45,2.75) 4(-4.45,2.25) 5(-4.45,1.75) 6(-4.45,1.25) 7(-4.45,0.75) 8(-4.45,0.25) 9(-4.45,-0.25) 10(-4.45,-0.75) 11(-4.45,-1.25) 12(-4.45,-1.75) 13(-4.45,-2.25) 14(-4.45,-2.75) 15(-4.45,-3.25) 16(-4.45,-3.75) 33(4.45,-3.75) 34(4.45,-3.25) 35(4.45,-2.75) 36(4.45,-2.25) 37(4.45,-1.75) 38(4.45,-1.25) 39(4.45,-0.75) 40(4.45,-0.25) 41(4.45,0.25) 42(4.45,0.75) 43(4.45,1.25) 44(4.45,1.75) 45(4.45,2.25) 46(4.45,2.75) 47(4.45,3.25) 48(4.45,3.75)
  rect 0.3x0.85 smd: 17(-3.75,-4.45) 18(-3.25,-4.45) 19(-2.75,-4.45) 20(-2.25,-4.45) 21(-1.75,-4.45) 22(-1.25,-4.45) 23(-0.75,-4.45) 24(-0.25,-4.45) 25(0.25,-4.45) 26(0.75,-4.45) 27(1.25,-4.45) 28(1.75,-4.45) 29(2.25,-4.45) 30(2.75,-4.45) 31(3.25,-4.45) 32(3.75,-4.45) 49(3.75,4.45) 50(3.25,4.45) 51(2.75,4.45) 52(2.25,4.45) 53(1.75,4.45) 54(1.25,4.45) 55(0.75,4.45) 56(0.25,4.45) 57(-0.25,4.45) 58(-0.75,4.45) 59(-1.25,4.45) 60(-1.75,4.45) 61(-2.25,4.45) 62(-2.75,4.45) 63(-3.25,4.45) 64(-3.75,4.45)
  rect 7.25x7.25 smd: 65(0,0)
  silkscreen extent -5,4.38 -4.75,4.62, body extent -4.55,-4.55 4.55,4.55, height 0.8
RESC1005X37N [mm]
  rect 0.7x0.6 smd: 1(-0.55,0) 2(0.55,0)
  body extent -0.5,-0.25 0.5,0.25, height 0.32
RESC1005X40N [mm]
  rect 0.75x0.6 smd: 1(-0.55,0) 2(0.55,0)
  body extent -0.5,-0.25 0.5,0.25, height 0.4
SON95P300X300X80-7N [mm]
  rect 0.85x0.4 smd: 1(-1.45,0.95) 2(-1.45,0) 3(-1.45,-0.95) 4(1.45,-0.95) 5(1.45,0) 6(1.45,0.95)
  rect 1.7x2.2 smd: 7(0,0)
  silkscreen extent -2,1.53 -1.75,1.77, body extent -1.5,-1.5 1.5,1.5, height 0.8
SON95P300X300X90-7N-D [mm]
  rect 0.85x0.3 smd: 1(-1.45,0.95) 2(-1.45,0) 3(-1.45,-0.95) 4(1.45,-0.95) 5(1.45,0) 6(1.45,0.95)
  rect 1.7x2.5 smd: 7(0,0)
  silkscreen extent -2,1.48 -1.75,1.72, body extent -1.55,-1.5 1.55,1.5, height 0.9
SOP50P488X110-10N [mm]
  rect 1.45x0.3 smd: 1(-2.225,1) 2(-2.225,0.5) 3(-2.225,0) 4(-2.225,-0.5) 5(-2.225,-1) 6(2.225,-1) 7(2.225,-0.5) 8(2.225,0) 9(2.225,0.5) 10(2.225,1)
  silkscreen extent -2.95,-1.5 1.15,1.5, body extent -2.44,-1.5 2.44,1.5, height 1.1
SOP65P640X120-20N [mm]
  rect 1.475x0.45 smd: 1(-2.938,2.925) 2(-2.938,2.275) 3(-2.938,1.625) 4(-2.938,0.975) 5(-2.938,0.325) 6(-2.938,-0.325) 7(-2.938,-0.975) 8(-2.938,-1.625) 9(-2.938,-2.275) 10(-2.938,-2.925) 11(2.938,-2.925) 12(2.938,-2.275) 13(2.938,-1.625) 14(2.938,-0.975) 15(2.938,-0.325) 16(2.938,0.325) 17(2.938,0.975) 18(2.938,1.625) 19(2.938,2.275) 20(2.938,2.925)
  silkscreen extent -3.67,-3.25 1.85,3.5, body extent -3.2,-3.25 3.2,3.25, height 1.13

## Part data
ADC1 ADC2: "Integrated Circuit", Manufacturer_Name="Analog Devices", Mouser Part Number=584-LTC2242CUP-12
C5 C6 C17 C20 C21 C22 C25 C26 C30 C32 C33 C39 C42 C43 C54: library part TMK105BJ104KV8F, "Capacitor", Manufacturer_Name="TAIYO YUDEN"
C7 C8 C29 C31: library part CGA3E1X7R1V105K080AC, "Capacitor", Manufacturer_Name=TDK
C28: library part CC0805KKX7R7BB225, "Capacitor", Manufacturer_Name="YAGEO (PHYCOMP)"
C52 C53: library part TMK105BJ104KV8F, "GJM1555C1H170FB01", Manufacturer_Name="TAIYO YUDEN"
IC2: "Integrated Circuit", Manufacturer_Name="Texas Instruments"
IC3: "Diode", Manufacturer_Name=LITTELFUSE
IC4: "Integrated Circuit", Manufacturer_Name=XILINX
R1 R2 R14 R15 R_new1 R_new2: library part APC0402RD-49R9FT10, "Resistor", Manufacturer_Name=WELWYN
R6 R7 R17 R18: library part CRCW04024R99FNED, "Resistor", Manufacturer_Name=Vishay
R16: library part MCS04020D1000BE000, "Resistor", Manufacturer_Name=Vishay
R31: library part ERJ-H2RD22R0X, "Resistor", Manufacturer_Name=Panasonic
R32: library part ERJ-H2RD10R0X, "Resistor", Manufacturer_Name=Panasonic
T1 T2: library part MABA-007159-000000, "Transformer", Manufacturer_Name=MACOM, Mouser2 Part Number=937-MABA007159000000

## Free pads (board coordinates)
  oct 49.21x49.21 hole 35.04: 0(1095,2830) 0(1095,2900) 0(1100,3085) 0(1100,3150) 0(1100,3325) 0(1100,3475) 0(1100,3575) 0(1100,3645) 0(1100,3790) 0(1102.05,3250) 0(1102.05,3400) 0(1102.95,3715) 0(1102.95,4125) 0(1177.05,3250) 0(1177.05,3325) 0(1177.05,3400) 0(1177.05,3475) 0(1177.05,4125) 0(1257.95,4125) 0(1332.95,4125) 0(1417.95,4125) 0(1500,4125) 0(1582.95,4125) 0(1662.95,4125) 0(2280,4125) 0(2355,4125) 0(2500,3715.43) 0(2500,3795) 0(2500,3950) 0(2500,4125) 0(2505,2725) 0(2505,2795) 0(2505,3140) 0(2505,3210) 0(2505,3295) 0(2505,3370) 0(2505,3450) 0(2505,3530)

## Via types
v1: diameter 11.81, hole 7.87, Top Layer to GND, 77 vias
v2: diameter 11.81, hole 7.87, Top Layer to Bottom Layer, 50 vias
v3: diameter 11.81, hole 7.87, GND to Bottom Layer, 47 vias
v4: diameter 11.81, hole 7.87, Top Layer to signal2, 33 vias
v5: diameter 11.81, hole 7.87, 3.3V to Bottom Layer, 27 vias
v6: diameter 11.81, hole 7.87, signal2 to Bottom Layer, 25 vias
v7: diameter 11.81, hole 7.87, Top Layer to 2.5V, 17 vias
v8: diameter 11.81, hole 7.87, 1.0V to Bottom Layer, 16 vias
v9: diameter 11.81, hole 7.87, Top Layer to 3.3V, 10 vias
v10: diameter 11.81, hole 7.87, 1.8V to Bottom Layer, 4 vias

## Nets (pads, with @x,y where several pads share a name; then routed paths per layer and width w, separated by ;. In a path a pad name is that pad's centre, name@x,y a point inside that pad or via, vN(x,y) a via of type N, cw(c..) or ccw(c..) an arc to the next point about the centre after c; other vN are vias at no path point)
1.0V: C58.2 LD49100PU10.4 LD49100PU10.5 pad.0@2280,4125 | length 188.2
  Top Layer w10: LD49100PU10.4@2160,4015.2 LD49100PU10.5@2160,4052.6 C58.2@2223.62,4052.6 ; C58.2@2227.52,4056.5 2227.52,4080 pad.0@2272.52,4125
  other v8: 1580,3362.48 1645,3362.48 1517.01,3363.07 1548.5,3394.57 1611.5,3394.57 1517.01,3426.06 1642.99,3426.06 1610,3457.48 1517.01,3489.06 1642.99,3489.06 1612.8,3521.02 1518.03,3551.02 1580,3552.48 1645,3552.48 1549.53,3582.52 1610,3585
1.8V: C64.2 LP38692-1.8.4 LP38692-1.8.5 pad.0@1582.95,4125 | length 588.8
  Top Layer w10: LP38692-1.8.4@1845,3943.7 LP38692-1.8.5@1845,3981.1 v2(1882.36,3981.1) C64.2@1882.36,3865.87
  Bottom Layer w10: pad.0@1585,4125 1635,4075 1862.36,4075 1882.36,4055 ; v2(1882.36,3981.1) 1882.36,4053.5
  other v10: 1485,3395 1485.51,3457.56 1485,3520 1485,3585
2.5V: ADC1.13 ADC1.14 ADC1.15 ADC1.26 ADC1.34 ADC1.42 ADC1.49 ADC1.59 ADC1.62 ADC1.63 ADC2.13 ADC2.14 ADC2.15 ADC2.26 ADC2.34 ADC2.42 ADC2.49 ADC2.59 ADC2.62 ADC2.63 C17.2 C18.2 C19.1 C20.2 C21.2 C22.2 C33.2 C39.2 C40.2 C41.1 C42.2 C43.2 C54.2 C56.1 C62.2 IC2.14 IC2.18 IC3.3 LP38692-2.5.4 LP38692-2.5.5 pad.0@1417.95,4125 | length 1945.6
  Top Layer w5: v7(1315,2595) 1350,2595 ; 1350,2604.09 ADC2.14@1379.61,2604.09 ; ADC2.15@1379.61,2584.41 1350,2584.41 1350,2623.78 ADC2.13@1379.61,2623.78 ; ADC2.63@1426.85,2887.56 1426.85,2900.31 1446.54,2920 ; ADC2.62@1446.54,2887.56 C40.2@1446.54,2931.54 ; C39.2@1584.33,2471.22 ADC2.26@1584.33,2537.17 ; ADC2.49@1702.44,2887.56 C41.1@1702.44,2940.59 ; ADC2.34@1730,2584.41 1770,2584.88 1789.4,2565.93 ; ADC2.42@1730,2740 1755.51,2740 1765.91,2729.61 1765.91,2689.09 1765.91,2673.85 C42.2@1786.57,2653.18 ; 1788.8,2565.93 C43.2@1789.4,2515 ; C20.2@1791.57,2946.65 1791.57,2895 1823.62,2862.95 v7(1854.8,2862.95) ; C21.2@1805,2685.79 1824.09,2705.21 ADC1.42@1854.8,2705.47 ; ADC1.49@1882.36,2559.8 1882.36,2517.44 1900,2499.8 v7(1923.31,2499.8) ; ADC1.26@2001.89,2911.61 C22.2@2001.89,2955 ; ADC1.62@2138.27,2559.8 2138.27,2544.69 2157.95,2525 ; v7(2157.95,2501.62) ADC1.63@2157.95,2559.8 ; ADC1.13@2205.2,2823.58 2239.53,2823.58 C17.2@2240.16,2966.89 ; ADC1.14@2205.2,2843.27 2239.84,2843.27 ; ADC1.15@2205.2,2863.58 2239.53,2863.58
  Top Layer w10: LP38692-2.5.4@1580,3898.7 LP38692-2.5.5@1580,3936.1 ; C62.2@1640,3940 v2(1640,3973.5) ; IC2.14@2190.67,3766.61 2231.61,3766.61 2245.87,3780.87 2245.87,3805 ; IC2.18@2195,3866.89 2228.98,3866.89 2245.87,3850 ; v7(2270,3850) 2245.87,3850 ; v7(2271.89,3805) 2245.87,3805 ; 2245.87,3805 2245.87,3850
  Bottom Layer w10: pad.0@1417.95,4125 1417.95,4090 1457.95,4050 1640,4050 1640,3965
  other v7: 1582.76,2480 1789.75,2518.11 2079.21,2559.8 1852.09,2704.25 1730,2741.89 1505.59,2887.56 1444.21,2942.36 1704.21,2942.36 2001.89,2960 2240,2966.69 2376.65,3555.63
3.3V: C48.1 C50.1 C60.2 IC2.3 IC2.7 LD49100PU33.4 LD49100PU33.5 pad.0@1257.95,4125 R37.2 R38.2 R39.1 R40.1 R41.1 R42.1 R43.1 R44.1 | length 891.1
  Top Layer w10: LD49100PU33.4@1270,3880.2 LD49100PU33.5@1270,3917.6 C60.2@1328.9,3917.6 ; C60.2@1325,3921.5 v2(1325,3985) ; 1914.92,3615.08 1914.92,3766.61 ; 1915,3615 2010,3615 ; IC2.7@1959.33,3766.61 1914.92,3766.61 ; IC2.3@1959.33,3868.98 1914.92,3868.98 1914.92,3766.61 ; C48.1@2050.39,3568.5 2010,3568.5 2010,3615 ; C50.1@2051.89,3615 2010,3615
  Bottom Layer w10: pad.0@1257.95,4122.05 1325,4055 v2(1325,3985)
  other v5: 1296.73,3205 1611.5,3205.59 1391.02,3237.09 1705.98,3237.09 1800.47,3268.58 1485,3270 1580,3300 1610,3330.98 1675,3330.98 1359.53,3331.57 1454.02,3363.07 1768.98,3363.07 1328.03,3426.06 1422.52,3457.56 1737.48,3457.56 1831.97,3489.06 1295,3520.98 1705,3552.48 1390,3552.52 1801.57,3583.54 1359.53,3646.54 1674.49,3646.54 1454.02,3678.03 1768.98,3678.03 1548.5,3709.53 1645,3740 1328.03,3741.02
  other v9: 1735,3043.35 1835,3057.75 1886.73,3057.75 1940,3059.24 1785,3063.35 1960,3198.19 2054.92,3570.39 2505,3613.35 2054.92,3614.49 2443.03,3846.65
5v: C57.2@1971.5,4091.5 C59.2 C61.2 C63.1 LD49100PU10.1 LD49100PU10.6 LD49100PU33.1 LD49100PU33.6 LP38692-1.8.1 LP38692-1.8.3 LP38692-1.8.6 LP38692-2.5.1 LP38692-2.5.3 LP38692-2.5.6 pad.0@1102.95,4125 | length 2207.7
  Top Layer w10: pad.0@1102.95,4117.87 1155.83,4065 1155.83,4045 ; 1155,4000 1155.83,4000 ; 1155,4045 1155.83,4045 ; LD49100PU33.1@1155.83,3955 1155.83,4000 ; LD49100PU33.6@1271.5,3956.5 1271.5,4000 1155.83,4000 ; C61.2@1400,4008.5 1490,4008.5 ; 1430,4008.5 1430,3921.5 1452.99,3898.5 LP38692-2.5.3@1465.63,3898.5 ; LP38692-2.5.1@1465.83,3973.5 1473.5,3981.18 1473.5,4045 ; 1473.5,4008.5 1580,4008.5 LP38692-2.5.6@1580,3973.5 ; C63.1@1695,3868.31 1695,3943.41 ; LP38692-1.8.3@1730.53,3943.41 1695,3943.41 ; 1730.83,4045 1473.5,4045 ; LP38692-1.8.6@1845,4018.5 1845,4065 ; C57.2@1970,4091.5 1890,4091.5 1890,4065 1845,4065 ; C57.2@1971.5,4090 LD49100PU10.1@2045.83,4090 ; LD49100PU10.1@2040,4095.83 2040,4130 2160,4130 LD49100PU10.6@2160,4090 ; 1155.83,4000 1155.83,4045 ; 1155.83,4045 1473.5,4045 ; 1695,3943.41 1695,4018.5 LP38692-1.8.1@1730.83,4018.5 1730.83,4065 1845,4065
ADC1_0: ADC1.40 | length 544.2
  signal2 w5: v6(1831.97,3268.58) 1847.4,3268.58 1860,3255.98 v4(1860,2745)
